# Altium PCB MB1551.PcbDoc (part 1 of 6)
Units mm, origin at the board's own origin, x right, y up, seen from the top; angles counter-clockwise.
Board outline 100 x 70 mm, 6 copper layers (Top Layer, Signal Layer 1, Signal Layer 2, Signal Layer 3, Signal Layer 4, Bottom Layer), stack 1.49 mm thick; 313 components, 266 nets, 1510 pads, 1089 vias.
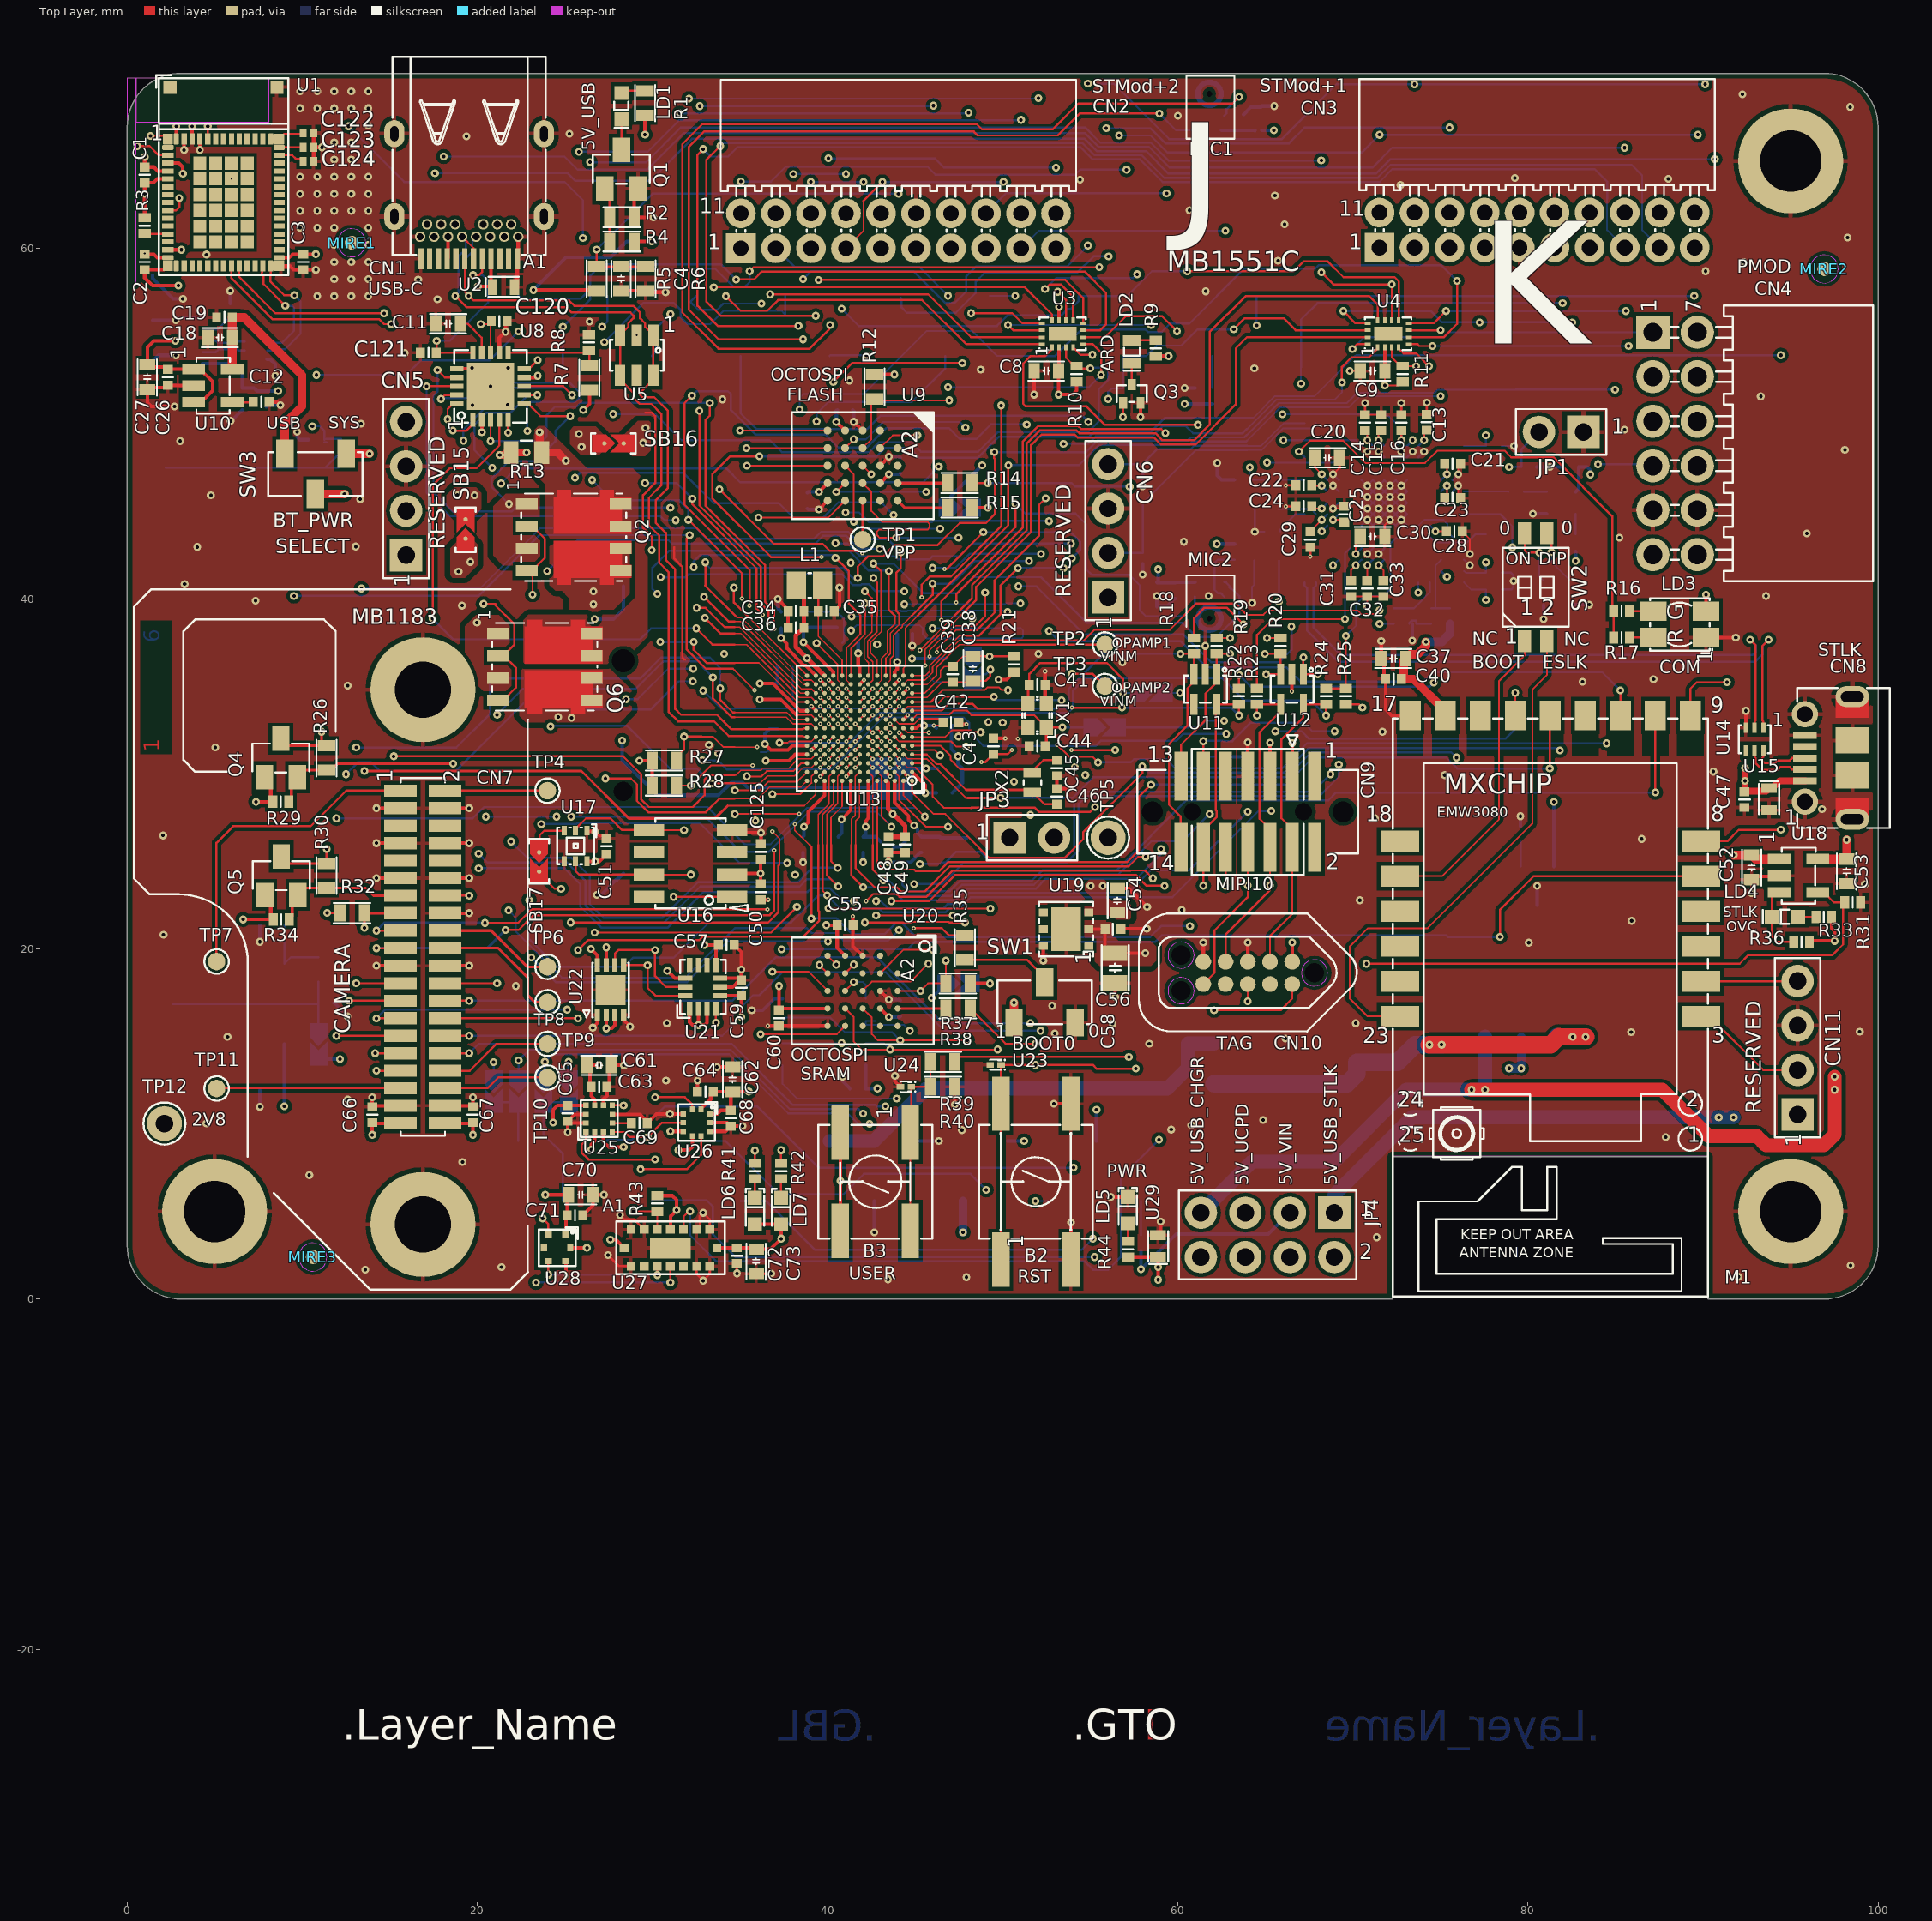
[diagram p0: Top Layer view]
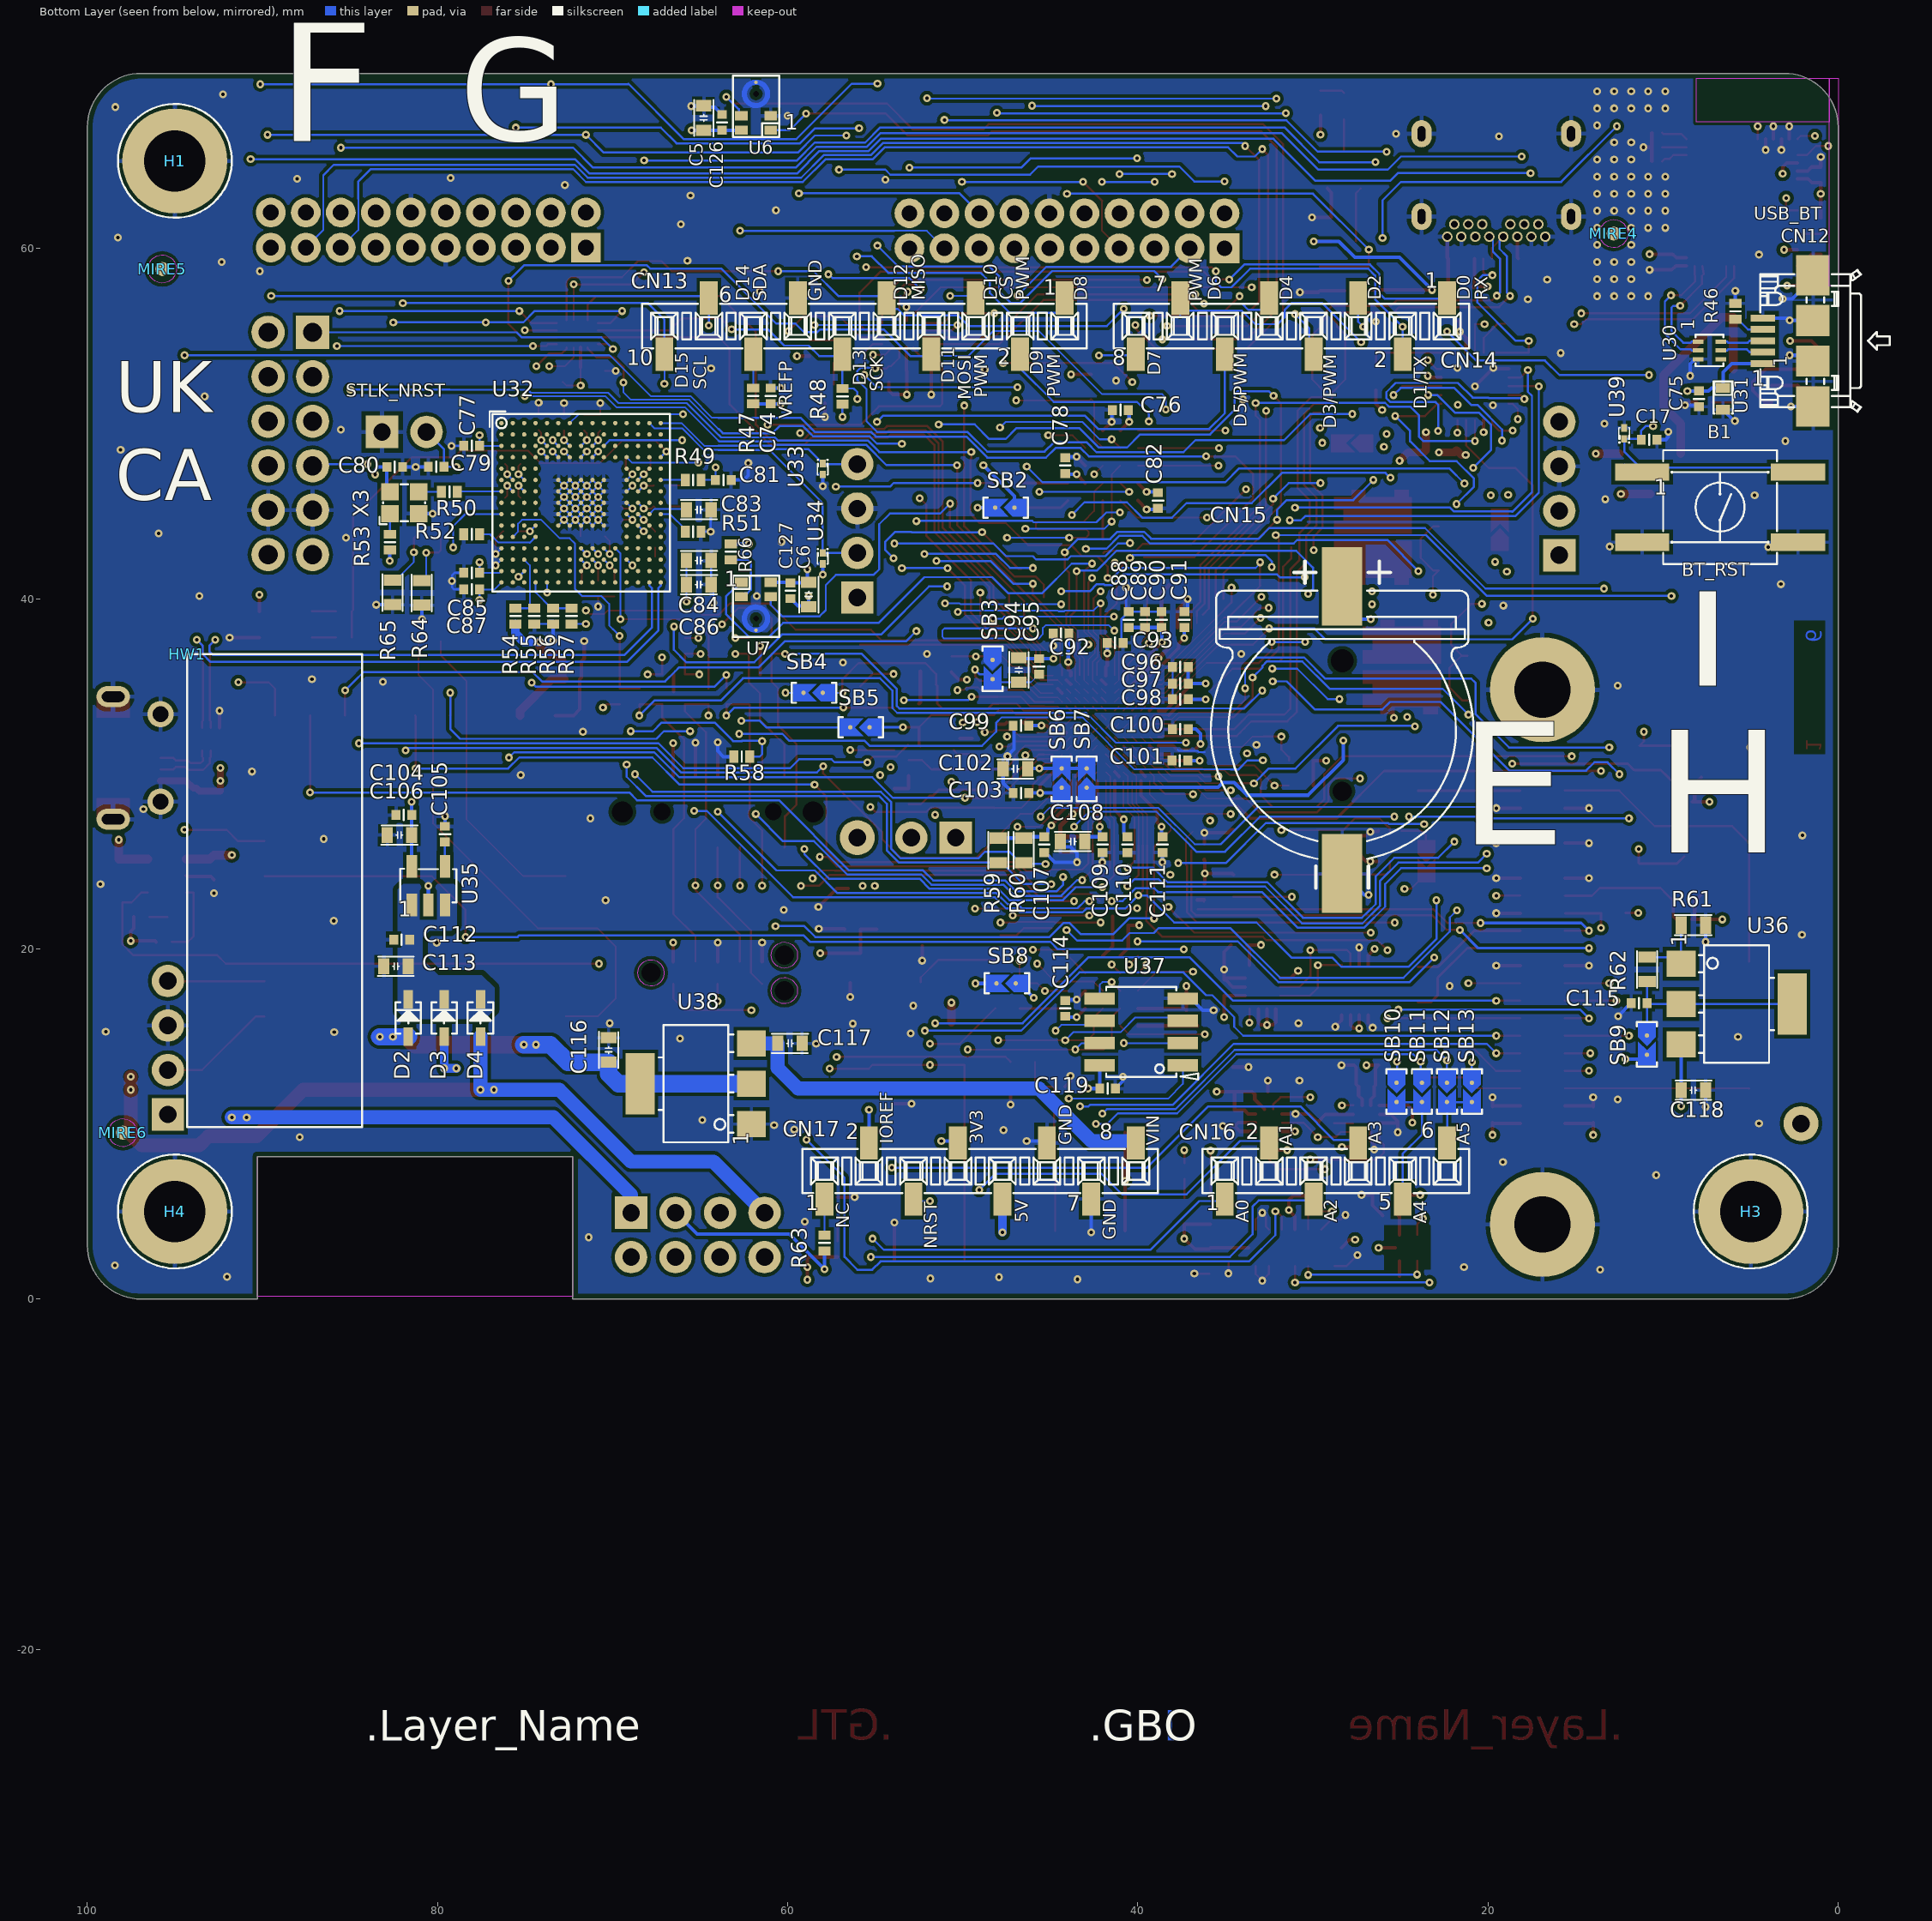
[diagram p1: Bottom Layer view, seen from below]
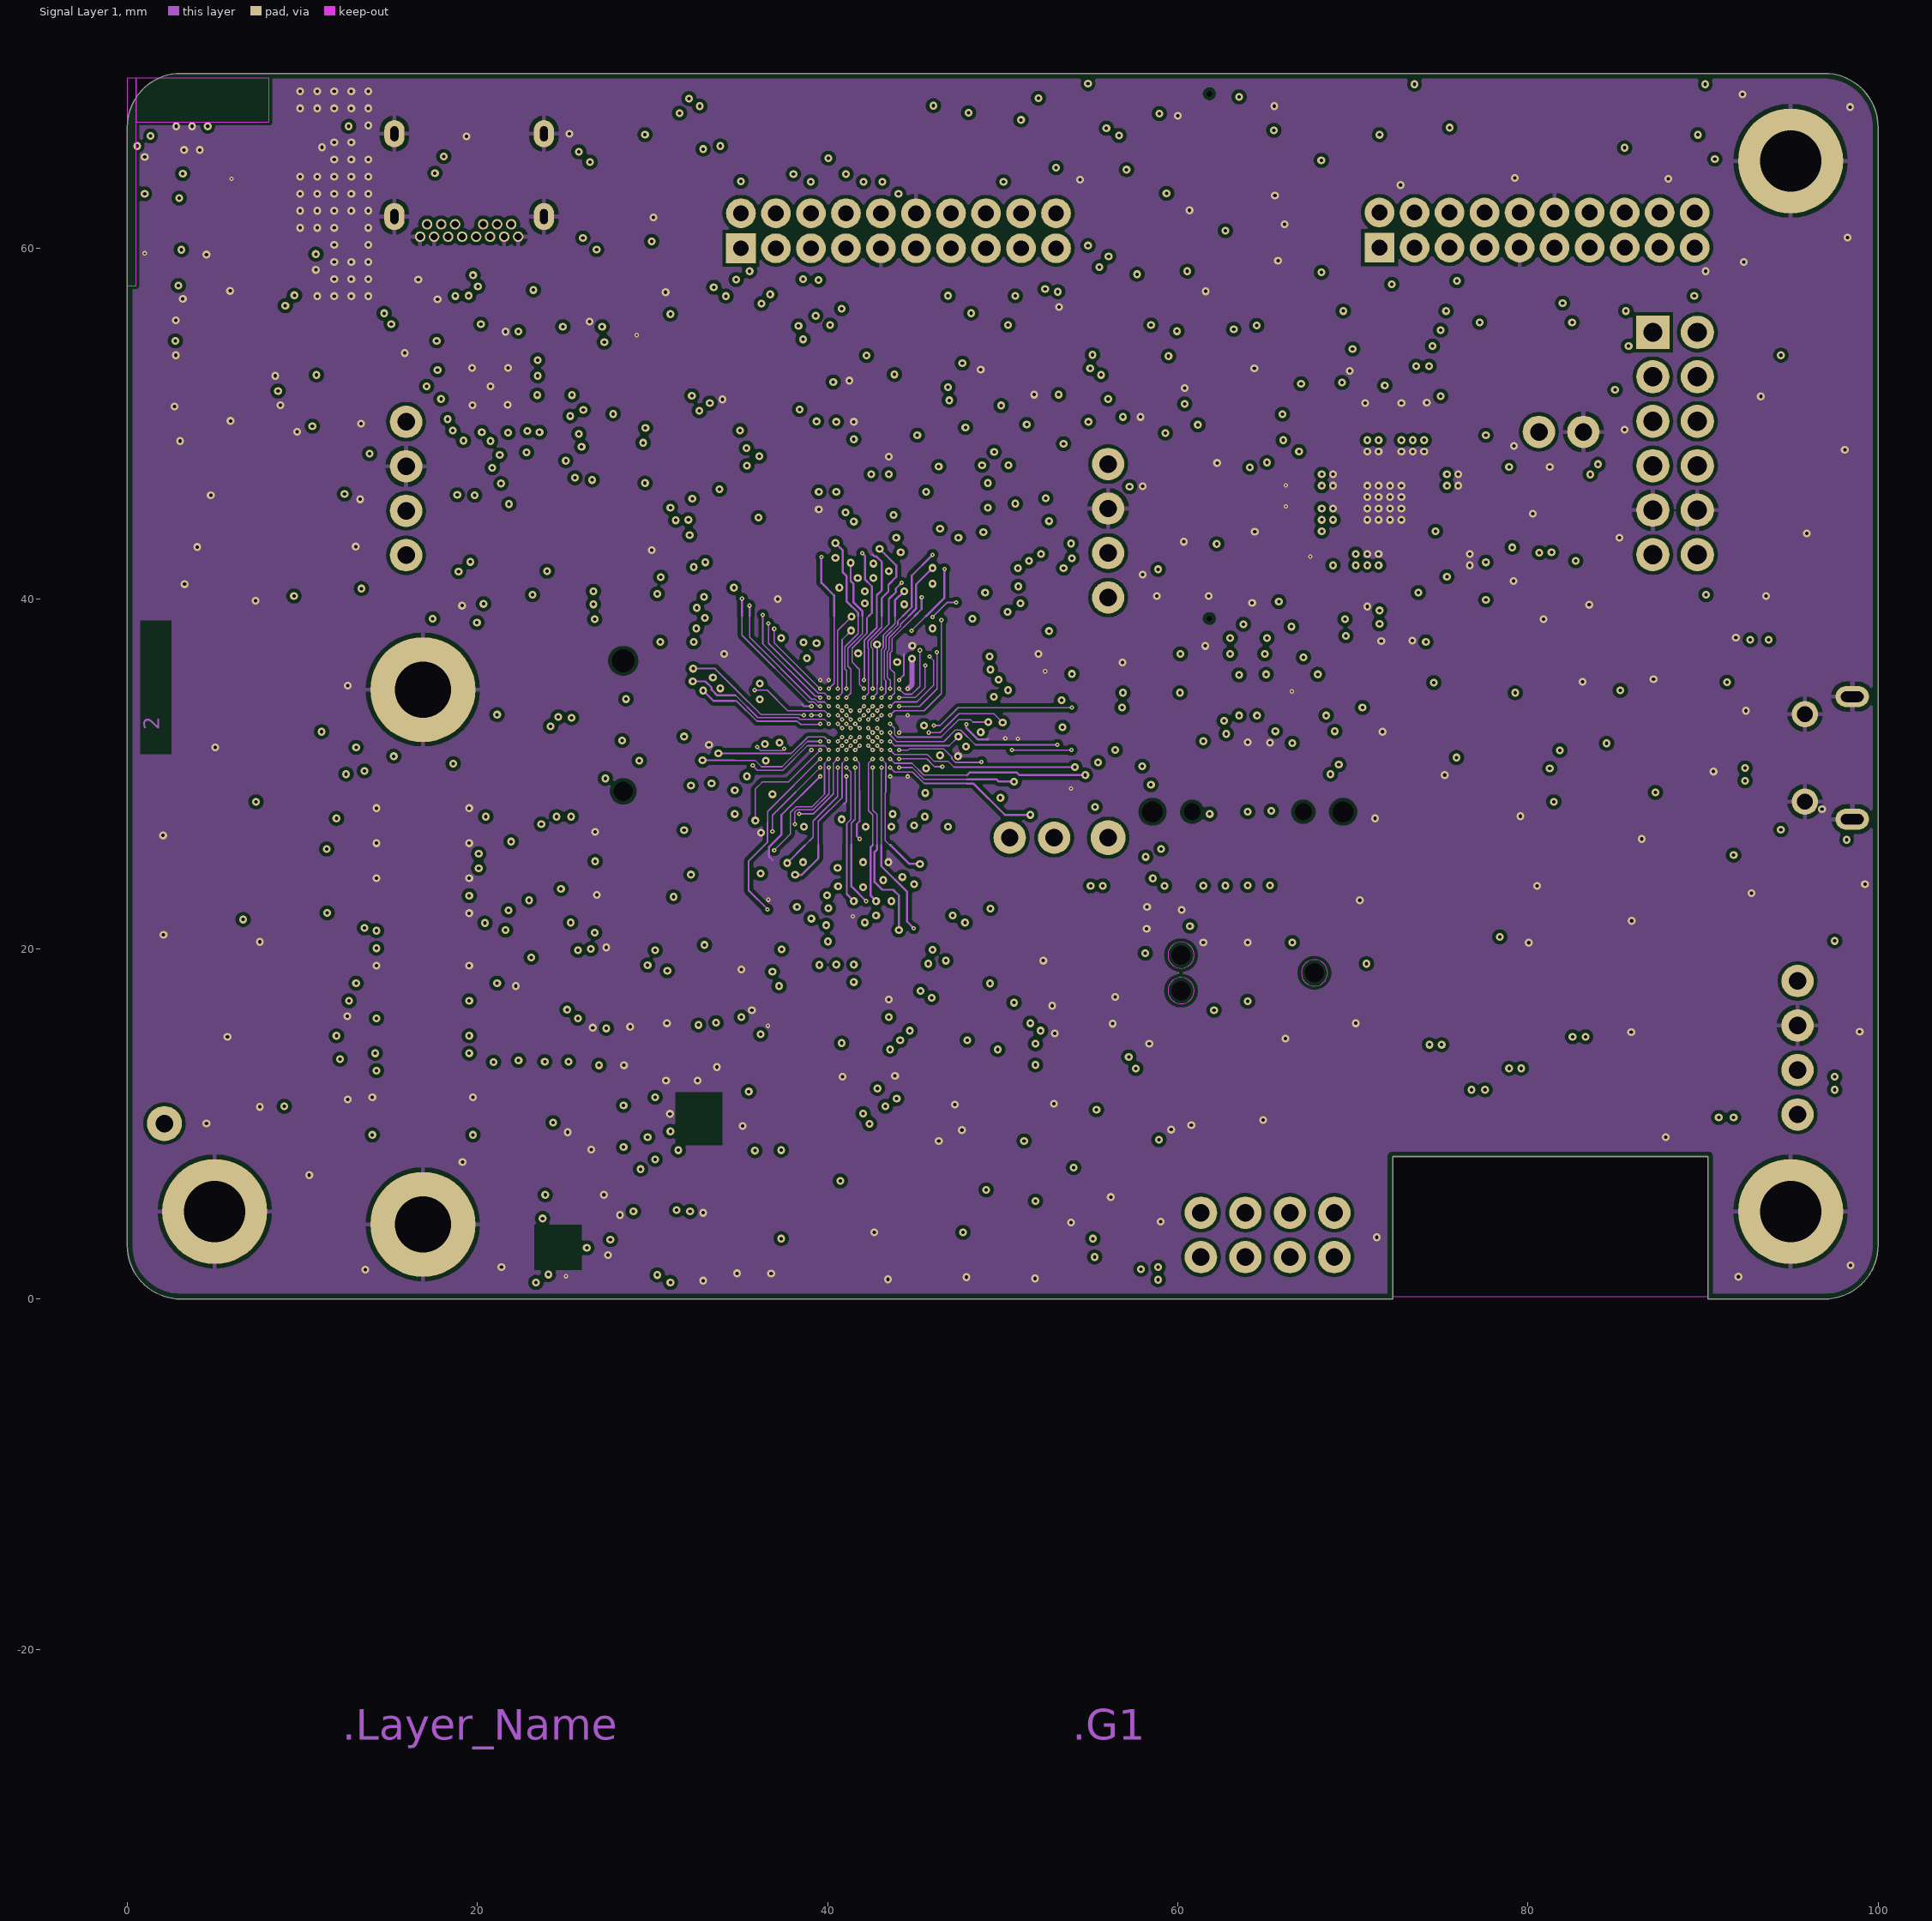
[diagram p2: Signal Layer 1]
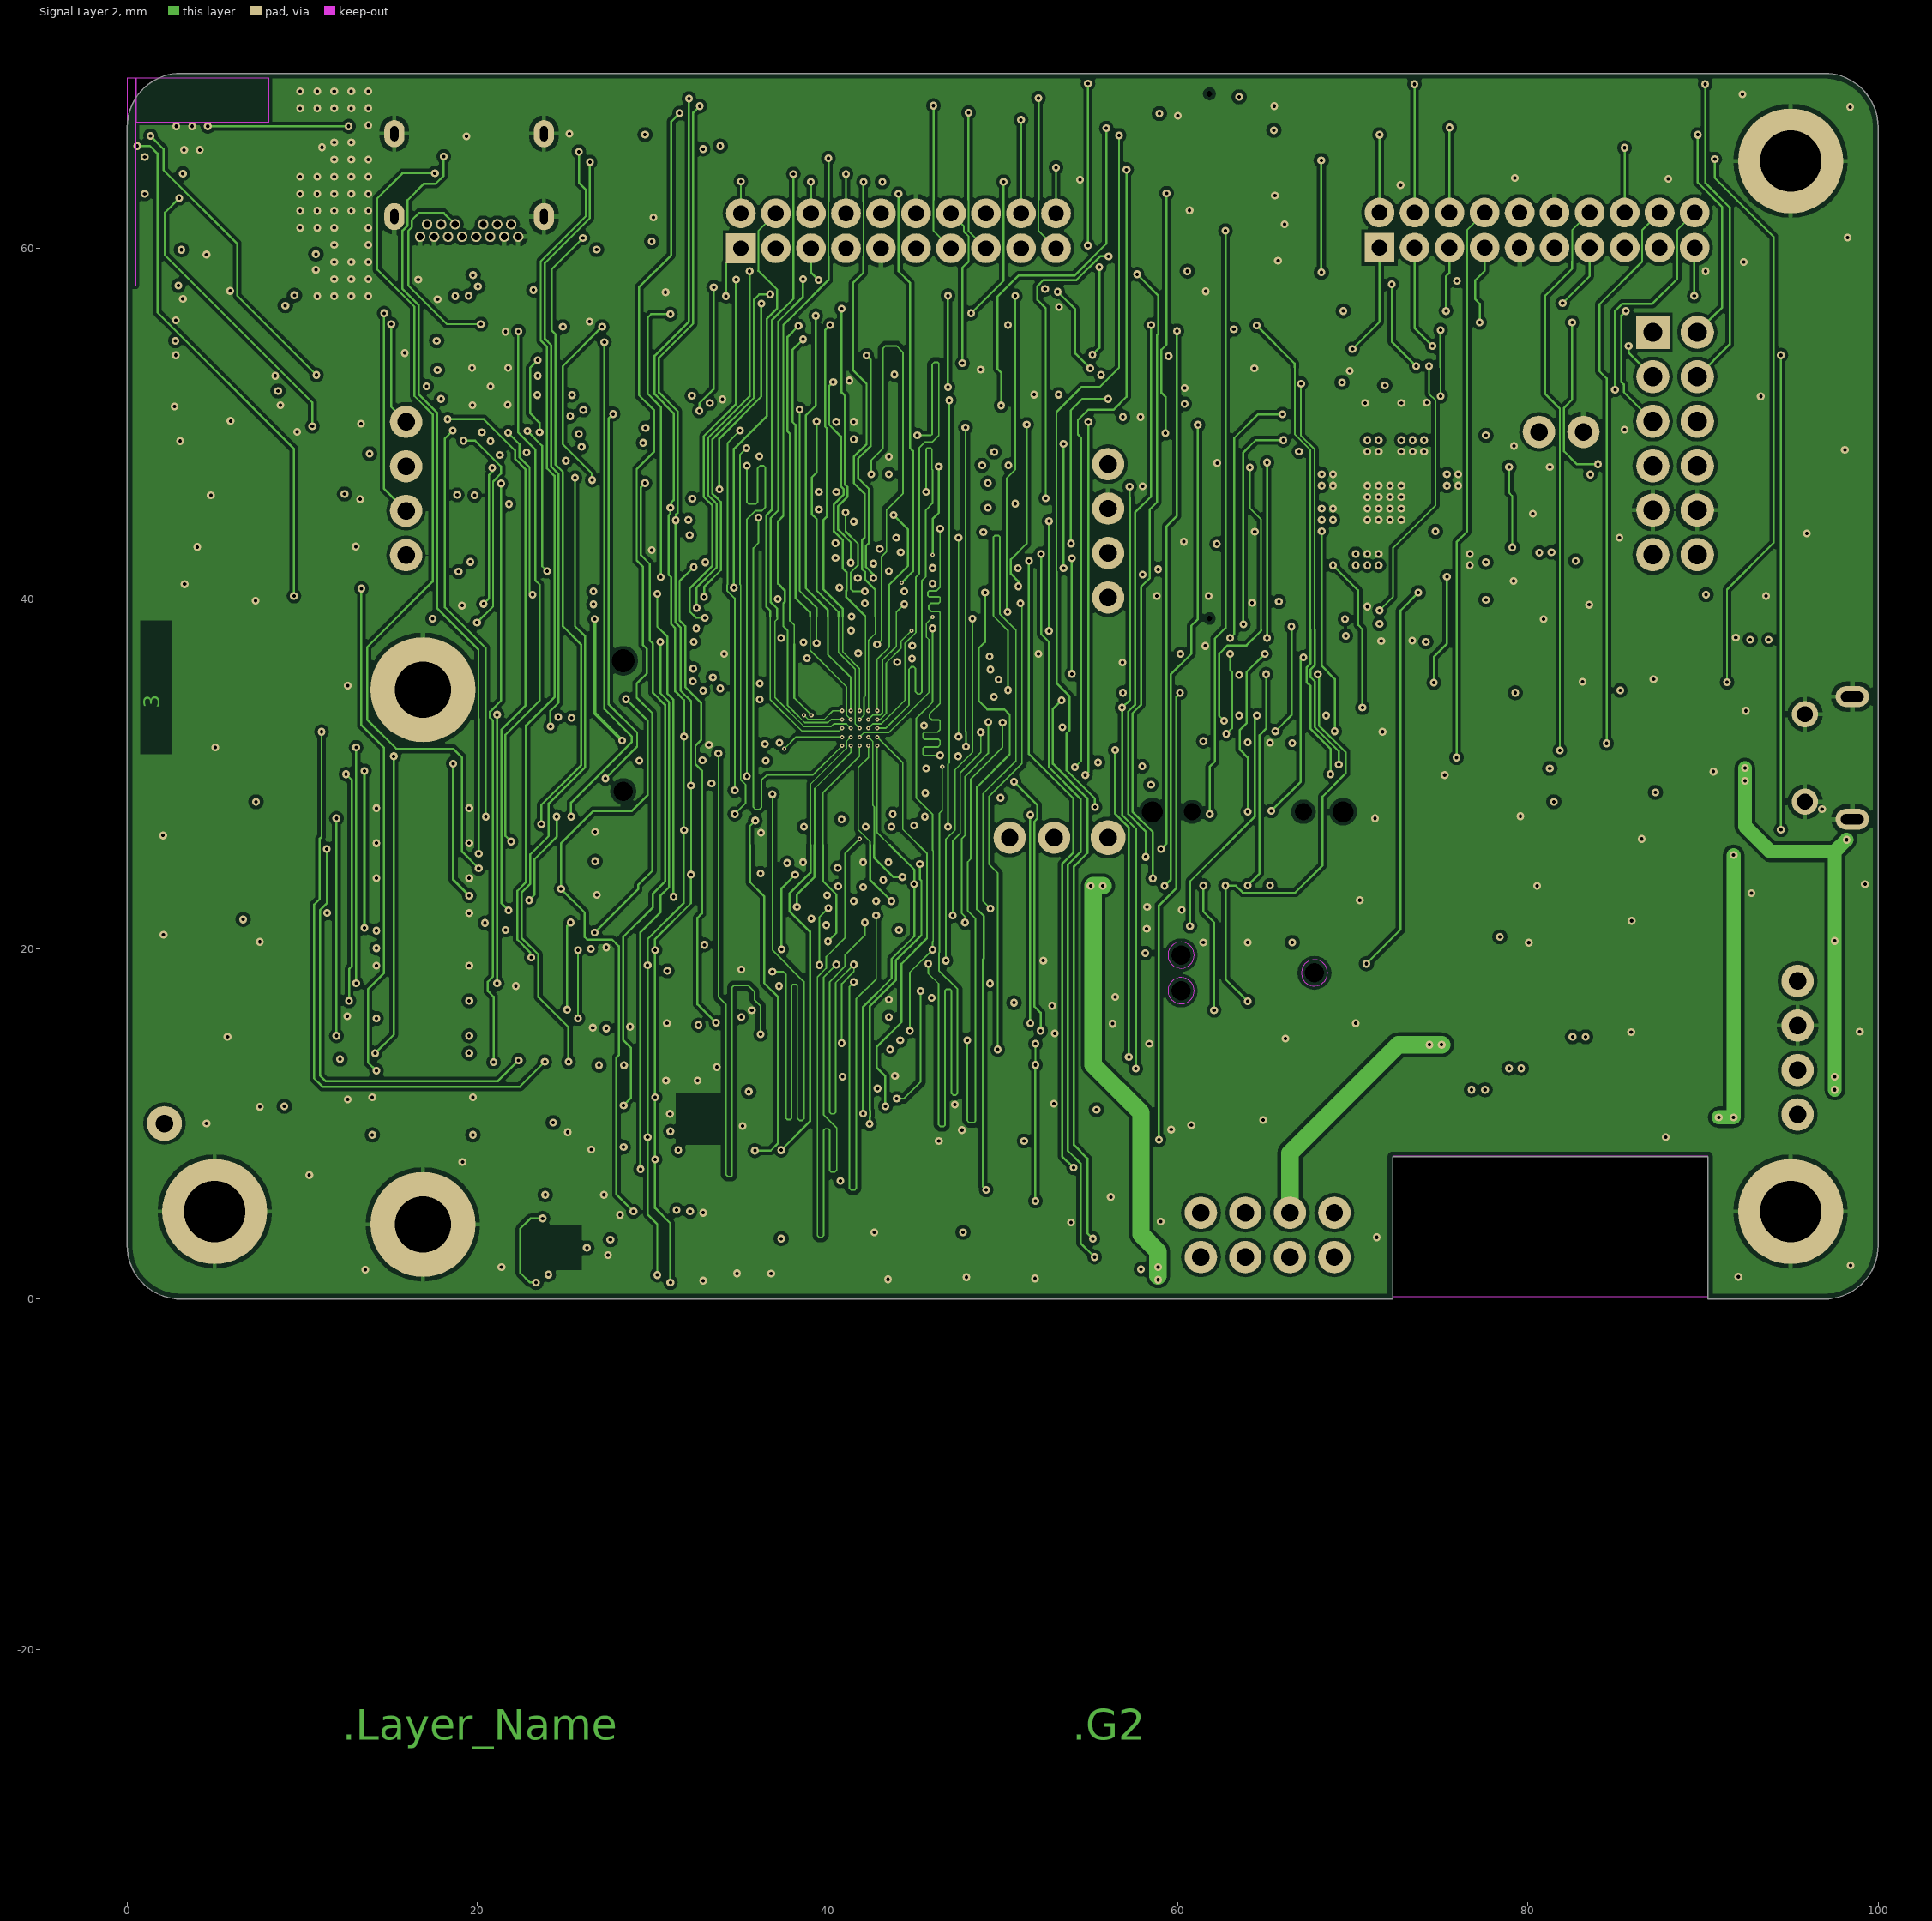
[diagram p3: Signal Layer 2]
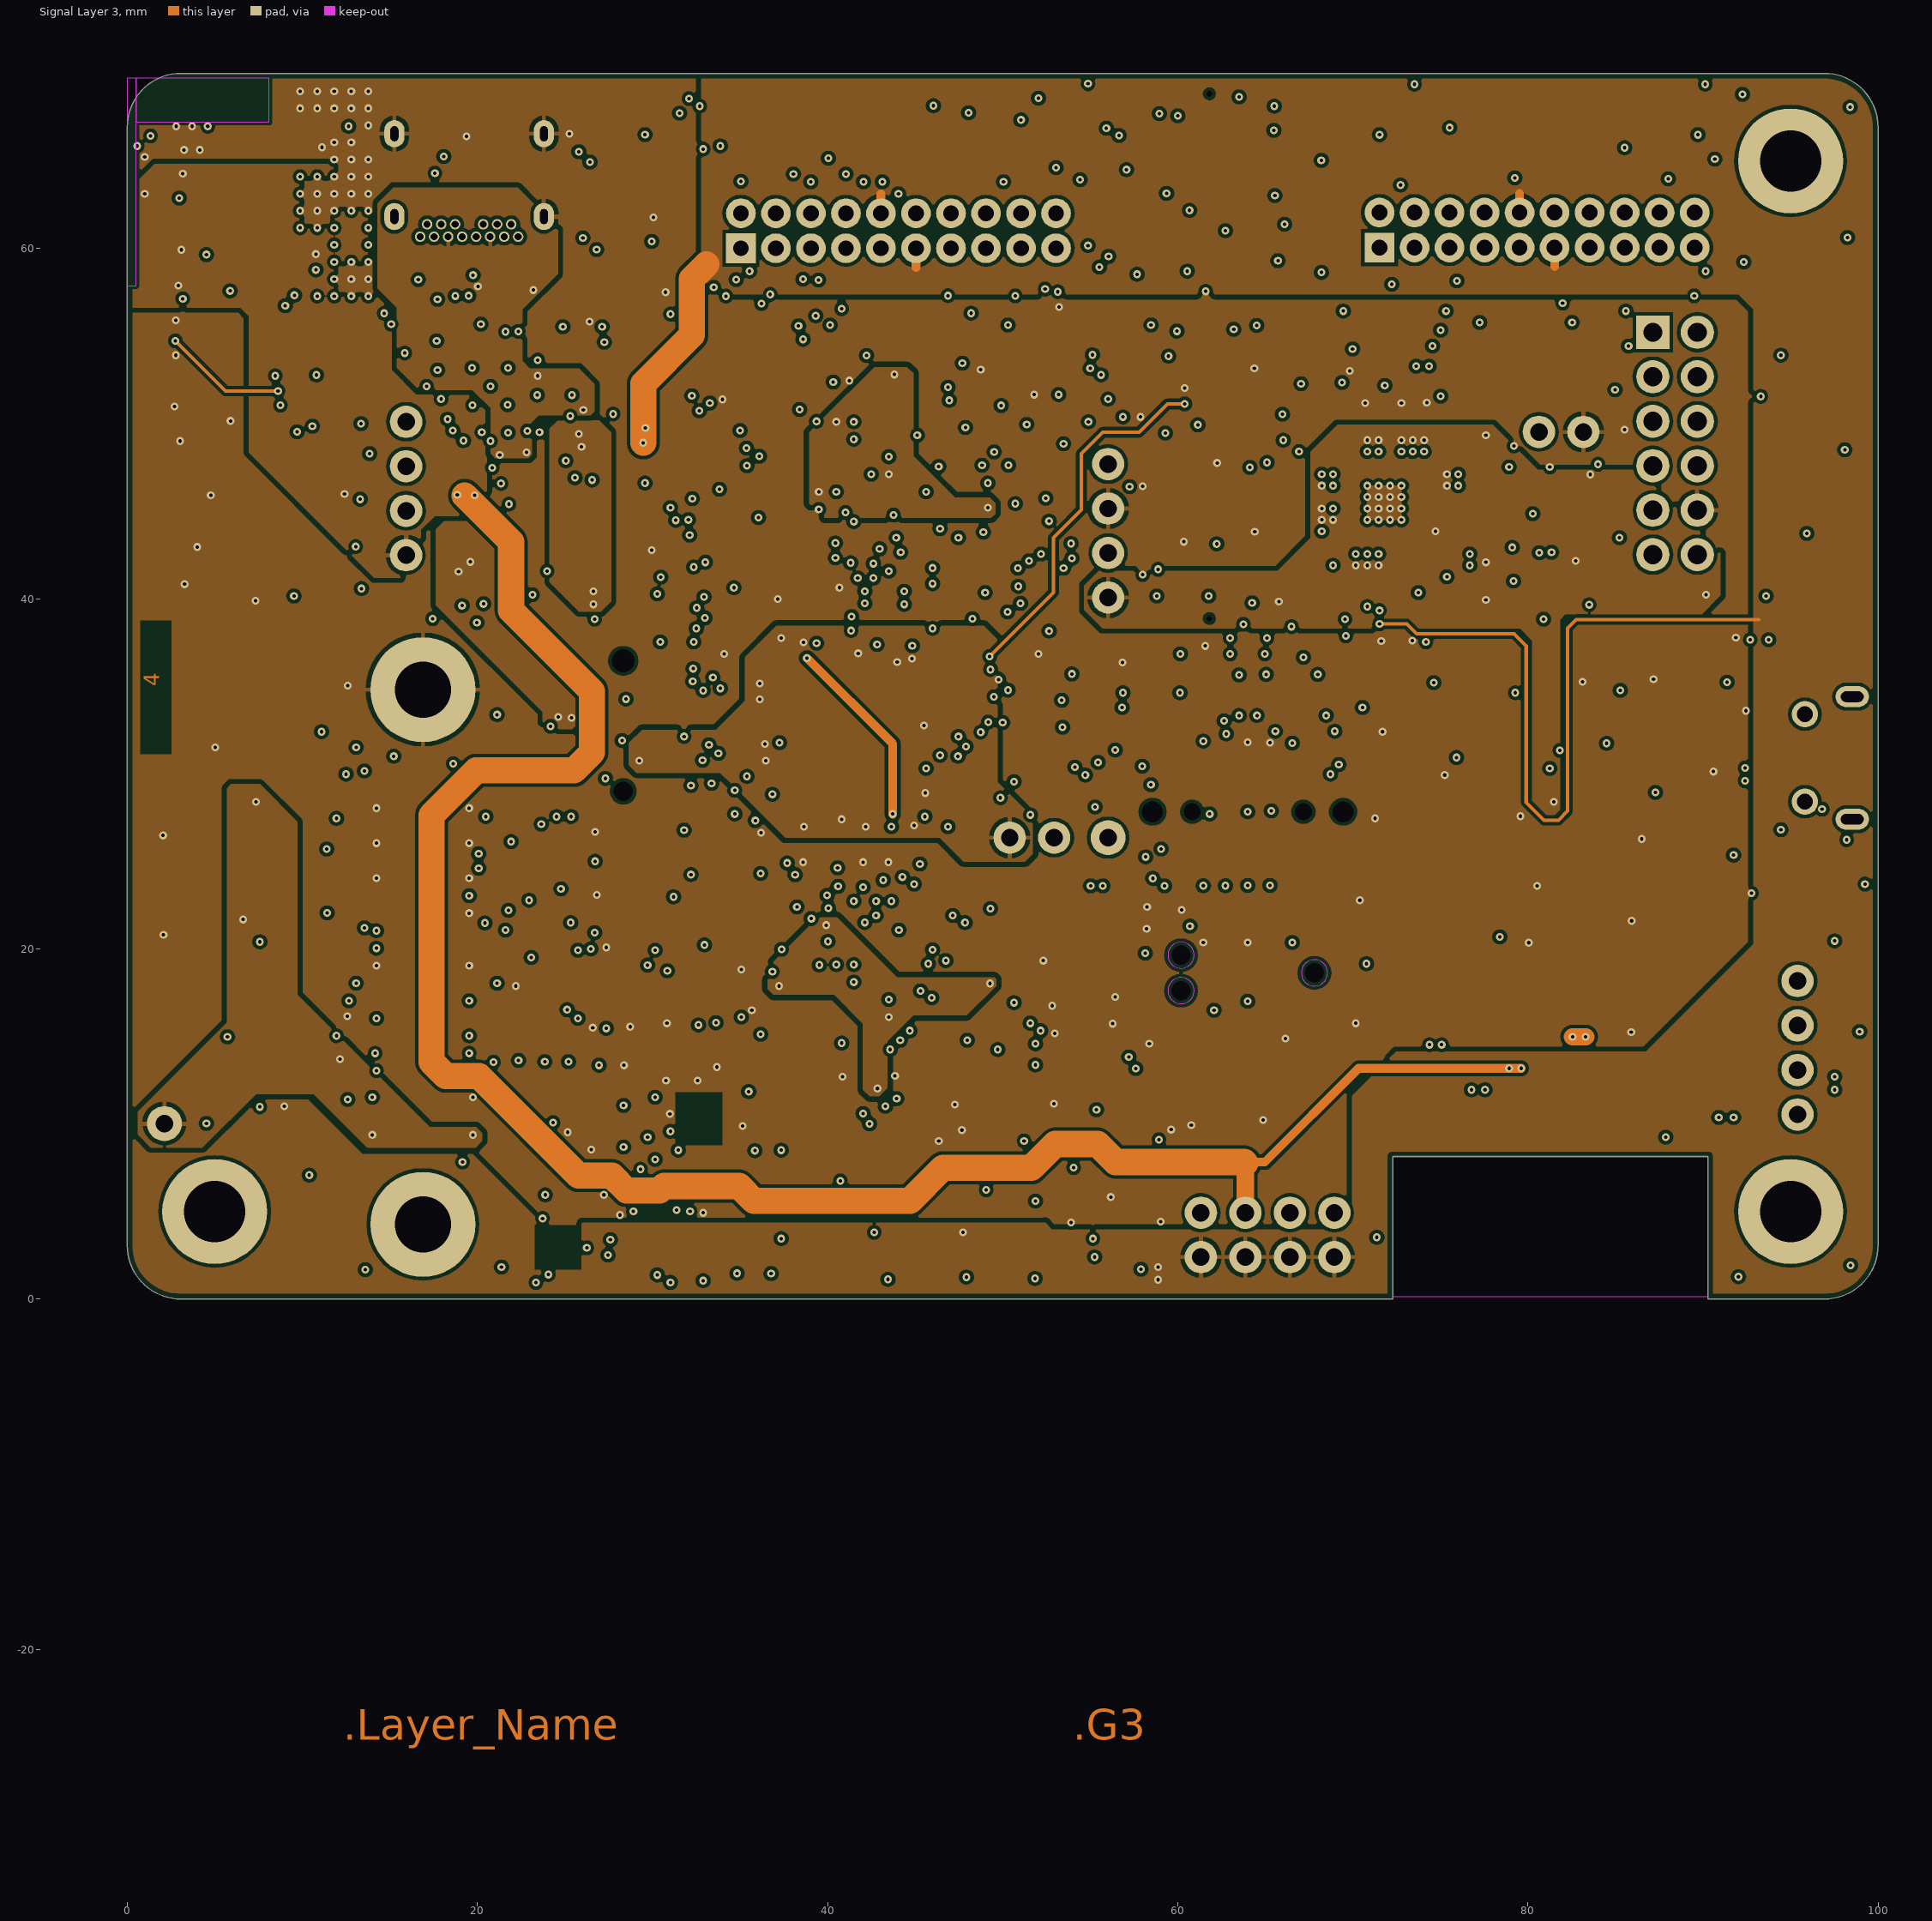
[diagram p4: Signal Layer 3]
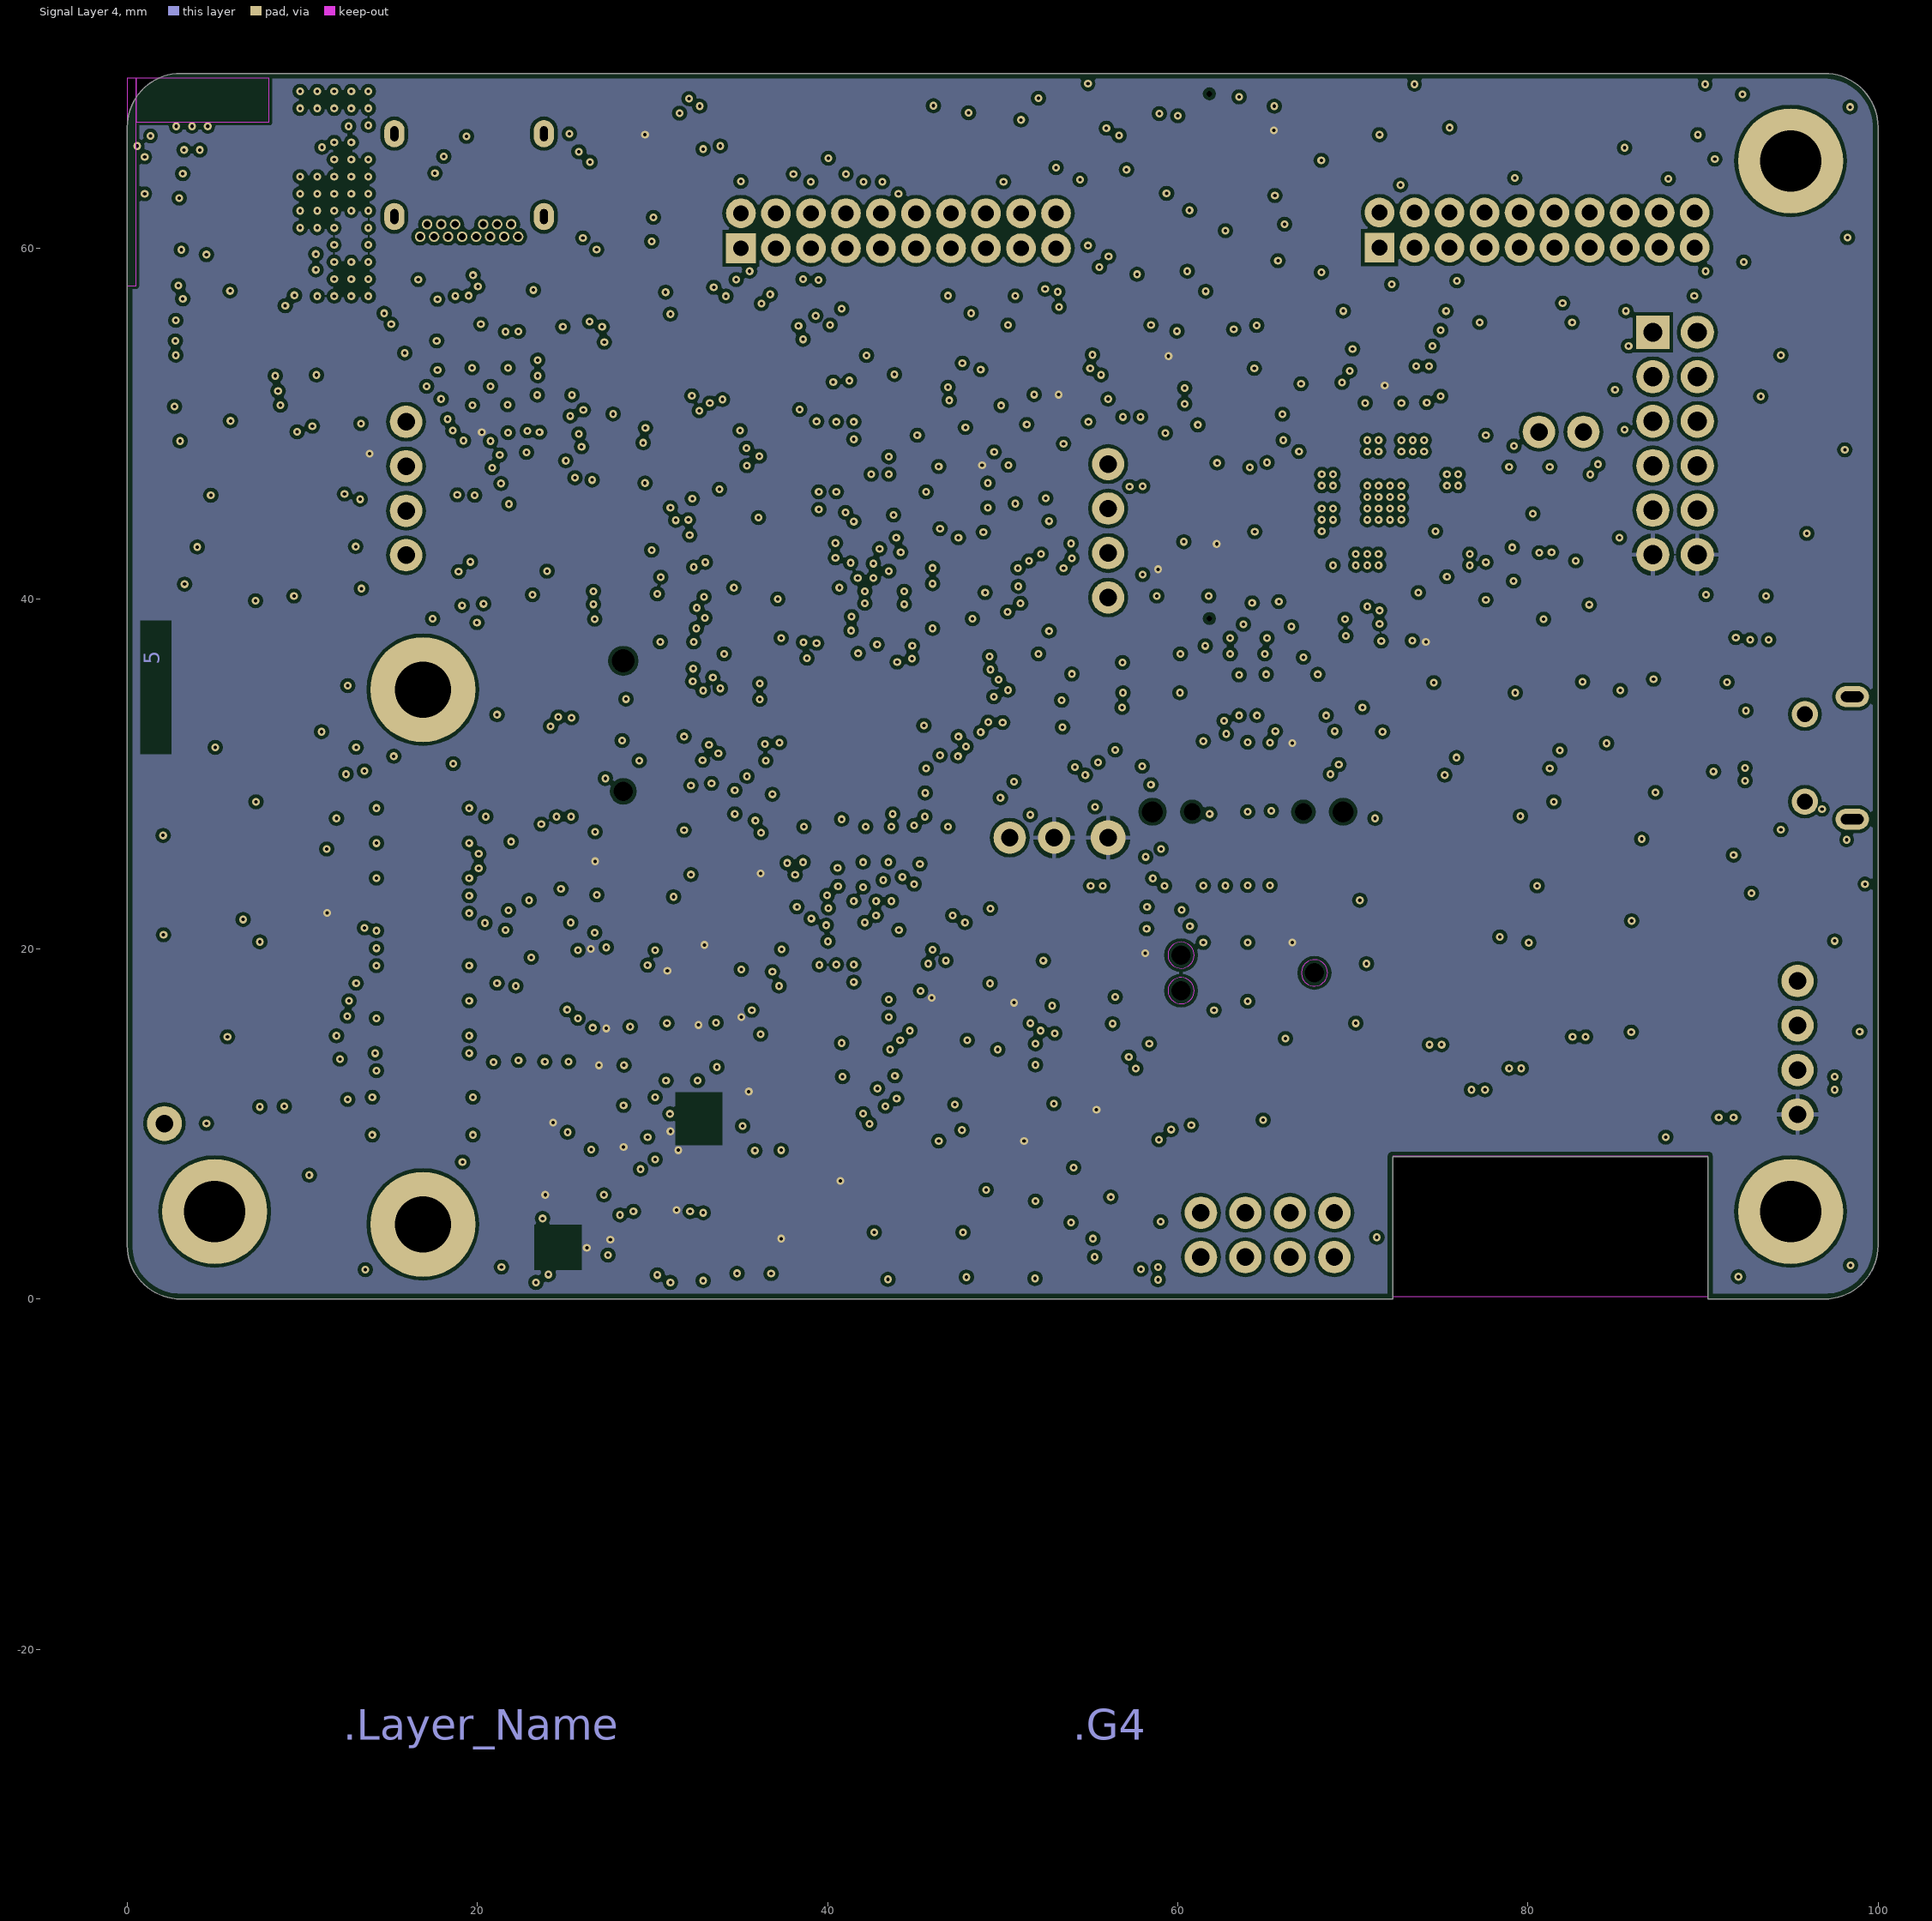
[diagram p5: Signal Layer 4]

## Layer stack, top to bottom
Top Solder: solder mask 0.015, Solder Resist, Dk 3.5
Top Layer: signal copper 0.035
Dielectric 1: dielectric 0.07, TU-768P, Dk 3.85
Signal Layer 1: signal copper 0.035
Dielectric2: dielectric 0.07, TU-768P, Dk 3.85
Signal Layer 2: signal copper 0.035
Dielectric3: dielectric 1, TU-768, Dk 4.5
Signal Layer 3: signal copper 0.035
Dielectric4: dielectric 0.07, TU-768P, Dk 3.85
Signal Layer 4: signal copper 0.035
Dielectric5: dielectric 0.07, TU-768P, Dk 3.85
Bottom Layer: signal copper 0.035
Bottom Solder: solder mask 0.015, Solder Resist, Dk 3.5

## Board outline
0,3.061 0,66.928 cw(c3.072,66.928) 3.072,70 96.927,70 cw(c96.927,66.927) 100,66.927 100,3.065 cw(c96.935,3.065) 96.935,0 90.28,0 90.28,8.125 72.28,8.125 72.28,0 3.061,0 cw(c3.061,3.061)

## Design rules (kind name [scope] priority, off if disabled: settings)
BoardOutlineClearance [All] p1: gap=0.3 ignorepadtopadclearanceinfootprint=FALSE except(0: Arc-SplitContinuation Track-SplitContinuation SMDPad-SplitContinuation THPad-SplitContinuation Via-SplitContinuation Fill-SplitContinuation Poly-SplitContinuation Region-SplitContinuation Text-SplitContinuation)
Clearance Clearance_Diff_90Ohms [InNetClass('Diff_90Ohms') vs InNet('GND')] p1: gap=0.12 ignorepadtopadclearanceinfootprint=FALSE except(0: Arc-Hole Track-Hole SMDPad-Hole THPad-Hole Via-Hole Fill-Hole Poly-Hole Region-Hole Text-Hole; 0.15: SMDPad-SMDPad; 0.2: Arc-Fill Arc-Poly Track-Fill SMDPad-THPad SMDPad-Fill SMDPad-Poly THPad-THPad THPad-Fill THPad-Poly Via-Fill Via-Poly Fill-Poly; 0.22: Track-Track Track-Poly; 0.3: Fill-Fill Poly-Poly)
Clearance Clearance_BGA_STLINK [WithinRoom('RoomDefinition_1')and TouchesRoom('RoomDefinition_1')] p2: gap=0.09 ignorepadtopadclearanceinfootprint=FALSE except(0: Arc-Hole Track-Hole SMDPad-Hole THPad-Hole Via-Hole Fill-Hole Poly-Hole Region-Hole Text-Hole; 0.15: SMDPad-SMDPad; 0.2: Arc-Fill Arc-Poly Track-Fill Track-Poly SMDPad-THPad SMDPad-Fill SMDPad-Poly THPad-THPad THPad-Fill THPad-Poly Via-Fill Via-Poly Fill-Poly; 0.3: Fill-Fill Poly-Poly)
Clearance Clearance_BGA_MCU [WithinRoom('RoomDefinition')and TouchesRoom('RoomDefinition')] p3: gap=0.085 ignorepadtopadclearanceinfootprint=FALSE except(0: Arc-Hole Track-Hole SMDPad-Hole THPad-Hole Via-Hole Fill-Hole Poly-Hole Region-Hole Text-Hole; 0.12: Track-Fill Via-Fill; 0.15: SMDPad-SMDPad; 0.2: Arc-Fill Arc-Poly Track-Poly SMDPad-THPad SMDPad-Fill SMDPad-Poly THPad-THPad THPad-Fill THPad-Poly Via-Poly Fill-Poly; 0.3: Fill-Fill Poly-Poly)
Clearance Clearance_50Ohms [InNetClass('50Ohms')] p4: gap=0.12 ignorepadtopadclearanceinfootprint=FALSE except(0: Arc-Hole Track-Hole SMDPad-Hole THPad-Hole Via-Hole Fill-Hole Poly-Hole Region-Hole Text-Hole; 0.2: Arc-Fill Arc-Poly SMDPad-THPad SMDPad-Fill SMDPad-Poly THPad-THPad THPad-Fill THPad-Poly Via-Fill Via-Poly Fill-Poly; 0.25: Arc-Track Track-Track Track-Fill Track-Poly Track-Region Track-Text SMDPad-SMDPad; 0.3: Fill-Fill Poly-Poly)
Clearance [All] p5: gap=0.12 ignorepadtopadclearanceinfootprint=FALSE except(0: Arc-Hole Track-Hole SMDPad-Hole THPad-Hole Via-Hole Fill-Hole Poly-Hole Region-Hole Text-Hole; 0.1: Track-THPad; 0.15: SMDPad-SMDPad; 0.2: Arc-Fill Arc-Poly Track-Fill Track-Poly SMDPad-THPad SMDPad-Fill SMDPad-Poly THPad-THPad THPad-Fill THPad-Poly Via-Fill Via-Poly Fill-Poly; 0.3: Fill-Fill Poly-Poly)
ComponentClearance [All] p1: gap=0.2 collisioncheckmode=3 verticalgap=0.2 showdistances=FALSE
DiffPairsRouting DiffPairsRouting_90Ohms [InDifferentialPairClass('Differential_Pairs_90Ohms')] p1: maxlimit=0.28 minlimit=0.2 mostfreqgap=0.2 toplayer_mingap=0.26 toplayer_maxgap=0.26 toplayer_prefgap=0.26 toplayer_minwidth=0.12 toplayer_maxwidth=0.12 toplayer_prefwidth=0.12 midlayer1_maxgap=0.2 midlayer1_minwidth=0.12 midlayer1_maxwidth=0.12 midlayer1_prefwidth=0.12 midlayer2_mingap=0.28 midlayer2_prefgap=0.28 midlayer2_minwidth=0.097 midlayer2_maxwidth=0.097 midlayer2_prefwidth=0.097 midlayer3_maxgap=0.2 midlayer3_minwidth=0.12 midlayer3_maxwidth=0.12 midlayer3_prefwidth=0.12 midlayer4_maxgap=0.2 midlayer4_minwidth=0.12 midlayer4_maxwidth=0.12 midlayer4_prefwidth=0.12 bottomlayer_mingap=0.26 bottomlayer_maxgap=0.26 bottomlayer_prefgap=0.26 bottomlayer_minwidth=0.12 bottomlayer_maxwidth=0.12 bottomlayer_prefwidth=0.12 maxuncoupledlength=12.7
HoleSize [All] p1: absolutevalues=TRUE maxlimit=10 minlimit=0.025 maxpercent=80.000 minpercent=20.000
HoleToHoleClearance [InDrillLayerPair('Top Layer - Bottom Layer') vs InDrillLayerPair('Top Layer - Bottom Layer')] p1: gap=0.5 allowstackedmicrovias=TRUE
MatchedLengths MatchedLengths_OctoSPI_F [InNetClass('OctoSPI_F')] p1: tolerance=7 checknetsindiffpair=FALSE checkdiffpairvsdiffpair=TRUE checkxsignals=TRUE checkothers=TRUE
MatchedLengths MatchedLengths_OctoSPI_R [InNetClass('OctoSPI_R')] p2: tolerance=7 checknetsindiffpair=FALSE checkdiffpairvsdiffpair=TRUE checkxsignals=TRUE checkothers=TRUE
MaxMinImpedance "Schematic Impedance Constraint_3" [InNet('USB_DEV_HS_P')] p1: minimum=85,00 maximum=95,00
MaxMinImpedance "Schematic Impedance Constraint_2" [InNet('USB_DEV_HS_N')] p2: minimum=85,00 maximum=95,00
MaxMinImpedance "Schematic Impedance Constraint_1" [InNet('USB_DEV_HS_CN_N')] p3: minimum=85,00 maximum=95,00
MaxMinImpedance "Schematic Impedance Constraint" [InNet('USB_DEV_HS_CN_P')] p4: minimum=85,00 maximum=95,00
MinimumSolderMaskSliver [All] p1: minsoldermaskwidth=0.1
PolygonConnect PolygonConnect_NO_FT [IsNamedPolygon('NO_FT')] p1: thpad.connectstyle=Relief thpad.reliefconductorwidth=0.25 thpad.reliefentries=4 thpad.polygonreliefangle="90 Angle" thpad.airgapwidth=0.25 smdpad.connectstyle=Direct smdpad.reliefconductorwidth=0.254 smdpad.reliefentries=4 smdpad.polygonreliefangle="90 Angle" smdpad.airgapwidth=0.254 via.connectstyle=Direct via.reliefconductorwidth=0.254 via.reliefentries=4 via.polygonreliefangle="90 Angle" via.airgapwidth=0.254
PolygonConnect [All] p2: thpad.connectstyle=Relief thpad.reliefconductorwidth=0.25 thpad.reliefentries=4 thpad.polygonreliefangle="90 Angle" thpad.airgapwidth=0.25 smdpad.connectstyle=Relief smdpad.reliefconductorwidth=0.2 smdpad.reliefentries=4 smdpad.polygonreliefangle="90 Angle" smdpad.airgapwidth=0.2 via.connectstyle=Direct via.reliefconductorwidth=0.2 via.reliefentries=4 via.polygonreliefangle="90 Angle" via.airgapwidth=0.2
RoomDefinition [InComponentClass('Room Definition 1') vs False] p1: confinementstyle=ConfineIn formatcopy=TRUE lockcomponents=FALSE outline 34.7,39 47.975,39 47.975,25.925 34.7,25.925
RoomDefinition RoomDefinition_1 [InComponentClass('Room Definition 1')] p2: confinementstyle=ConfineIn formatcopy=TRUE lockcomponents=FALSE outline 79.325,38.25 63.95,38.25 63.95,53.2 79.325,53.2
RoutingVias RoutingVias_SL4/BOTTOM [InDrillLayerPair('Signal Layer 4 - Bottom Layer')] p1: holewidth=0.1 width=0.25 viastyle="Through Hole" minholewidth=0.1 minwidth=0.25 maxholewidth=0.1 maxwidth=0.25
RoutingVias RoutingVias_SL3/SL4 [InDrillLayerPair('No Drill Pair')] p2: holewidth=0.1 width=0.25 viastyle="Through Hole" minholewidth=0.1 minwidth=0.25 maxholewidth=0.1 maxwidth=0.25
RoutingVias RoutingVias_SL1/SL2 [InDrillLayerPair('Signal Layer 1 - Signal Layer 2')] p3: holewidth=0.1 width=0.25 viastyle="Through Hole" minholewidth=0.1 minwidth=0.25 maxholewidth=0.1 maxwidth=0.25
RoutingVias RoutingVias_TOP/SL1 [InDrillLayerPair('Top Layer - Signal Layer 1')] p4: holewidth=0.1 width=0.25 viastyle="Through Hole" minholewidth=0.1 minwidth=0.25 maxholewidth=0.1 maxwidth=0.25
RoutingVias RoutingVias_TOP/BOTTOM [InDrillLayerPair('Top Layer - Bottom Layer')] p5: holewidth=0.2 width=0.45 viastyle="Through Hole" minholewidth=0.2 minwidth=0.45 maxholewidth=0.2 maxwidth=0.45
SilkToSilkClearance [All] p1: silktosilkclearance=0.2
SilkToSolderMaskClearance [IsPad] p1: minsilkscreentomaskgap=0.2 clearancetoexposedcopper=TRUE
SolderMaskExpansion [All] p1: expansion=0.102 istentingtop=FALSE
Width Width_BGA_STLINK [WithinRoom('RoomDefinition_1')and TouchesRoom('RoomDefinition_1')] p1: maxlimit=0.25 minlimit=0.09 preferedwidth=0.1
Width Width_BGA_MCU [WithinRoom('RoomDefinition')and TouchesRoom('RoomDefinition')] p2: maxlimit=0.25 minlimit=0.08 preferedwidth=0.1
Width Width_50Ohms [InNetClass('50Ohms')] p3: maxlimit=0.1 minlimit=0.08 preferedwidth=0.09 toplayer_minwidth=0.1 toplayer_prefwidth=0.1 midlayer1_maxwidth=0.08 midlayer1_prefwidth=0.08 midlayer2_minwidth=0.09 midlayer2_maxwidth=0.09 midlayer3_minwidth=0.09 midlayer3_maxwidth=0.09 midlayer4_maxwidth=0.08 midlayer4_prefwidth=0.08 bottomlayer_minwidth=0.1 bottomlayer_prefwidth=0.1 minimp=50.000000 maximp=50.000000 favimp=50.000000
Width Width_Alim [InNetClass('Alim')] p4: maxlimit=1.5 minlimit=0.12 preferedwidth=0.2
Width [All] p5: maxlimit=1 minlimit=0.1 preferedwidth=0.12
23 further rules are at their usual default settings.

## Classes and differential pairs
net class Diff_90Ohms: NetCN12_2 NetCN12_3 USB.C_N USB.C_P USB_DEV_HS_CN_N USB_DEV_HS_CN_P USB_DEV_HS_N USB_DEV_HS_P USB_DM USB_DP
net class Alim_500µm: 2V8 3V3_STLK
net class Alim_1,5mm: 3V3
net class Alim_800µm: 5V_USB_CHGR 5V_USB_STLK VBUS_C VIN
net class Alim_1mm: 5V 5V_VIN
net class OctoSPI_F: OCTOSPI.F_CLK_P OCTOSPI.F_DQS OCTOSPI.F_IO0 OCTOSPI.F_IO1 OCTOSPI.F_IO2 OCTOSPI.F_IO3 OCTOSPI.F_IO4 OCTOSPI.F_IO5 OCTOSPI.F_IO6 OCTOSPI.F_IO7 OCTOSPI.F_NCS
net class OctoSPI_R: OCTOSPI.R_CLK_P OCTOSPI.R_DQS OCTOSPI.R_IO0 OCTOSPI.R_IO1 OCTOSPI.R_IO2 OCTOSPI.R_IO3 OCTOSPI.R_IO4 OCTOSPI.R_IO5 OCTOSPI.R_IO6 OCTOSPI.R_IO7 OCTOSPI.R_NCS
net class 50Ohms: OCTOSPI.F_CLK_P OCTOSPI.F_DQS OCTOSPI.F_IO0 OCTOSPI.F_IO1 OCTOSPI.F_IO2 OCTOSPI.F_IO3 OCTOSPI.F_IO4 OCTOSPI.F_IO5 OCTOSPI.F_IO6 OCTOSPI.F_IO7 OCTOSPI.F_NCS OCTOSPI.R_CLK_P OCTOSPI.R_DQS OCTOSPI.R_IO0 OCTOSPI.R_IO1 OCTOSPI.R_IO2 OCTOSPI.R_IO3 OCTOSPI.R_IO4 OCTOSPI.R_IO5 OCTOSPI.R_IO6 OCTOSPI.R_IO7 OCTOSPI.R_NCS
component class U_WIFI&BT_INTERPOSERS: B3 C1 C16 C18 C30 C39 C43 C53 C82 C101 C103 C108 CN3 CN6 HW9 M1 R37 R39 U1 U2 U36
component class U_USB_TYPEC: C42 C45 C89 C90 CN4 JP1 LD1 Q1 Q2 R1 R2 R5 R6 R13 R20 R27 R40 U2 U5 U8
component class U_STMod+: C9 C101 CN3 CN4 R11 R13 U5 U31
component class U_ST_LINK_V3E: C1 C9 C12 C14 C15 C23 C30 C32 C39 C53 C76 C79 C80 C81 C83 C84 C85 C86 C87 C90 C92 C93 C94 C96 C98 C99 C104 C105 C106 C108 C109 C111 C112 CN3 CN8 CN9 CN10 D2 D3 D4 HW8 JP1 LD1 LD2 R5 R15 R17 R18 R20 R22 R24 R27 R34 R41 R44 R49 R50 R51 R52 R53 R54 R55 R56 R57 R58 R61 U11 U12 U18 U22 U31 U32 U33 U34 U38 X3
component class U_OCTOSPI: C30 C53 C61 C76 C82 C114 C118 R12 R13 R14 R37 R38 SB2 SB8 TP1 U2 U5 U20
component class U_MEMs: C50 C53 C59 C60 C61 C63 C64 C65 C66 C69 C70 C71 C72 C80 C114 R41 R56 U11 U12 U13 U18 U19 U21 U26 U33 U34
component class U_Mechanical_Parts: H1 H3 H4 HW3 HW4 HW5
component class U_MCU_PWR: C9 C12 C16 C30 C32 C34 C35 C39 C48 C53 C89 C90 C92 C93 C94 C96 C97 C98 C100 C101 C102 C103 C105 C108 C109 C111 C118 C119 L1 SB3 SB7
component class U_MCU_IO: R20 R24 R27 R59 TP1 TP2 U33
component class U_MCU_CLOCK_&_RESET: B2 B3 C4 C39 C42 C43 C45 C61 HW1 HW2 LD2 LD6 R35 R37 R40 R52 R54 U20 U24 X1 X2
component class U_Camera: C53 C61 CN7 Q3 Q4 R24 R30 R34 R44 R52 TP4 TP5 TP6 TP7 TP8 TP9 TP10
component class U_BOARD_PWR: C50 C56 C69 C103 C108 C114 C118 HW1 JP1 LD5 R24 R44 R62 SB10 TP5 TP10 U12 U26 U36 U38
component class U_AUDIO: C39 C61 U2 U20
component class U_ARDUINO: C92 CN6 CN10 CN11 LD2 Q3 R5 R24 R48 R52 SB10 SB11 SB12 SB13
net class Alim: 2V8 3V3 3V3_BT 3V3_STLK 5V 5V_UCPD 5V_USB_CHGR 5V_USB_STLK 5V_VIN AGND GND VBUS_BT VBUS_C VDD_MCU VDD_OCTOSPI_FLASH VDD_OCTOSPI_SRAM VIN VREFP
differential pair USB_FS: +USB.C_P -USB.C_N
differential pair USB_DEV_HS: +USB_DEV_HS_P -USB_DEV_HS_N
differential pair USB_DEV_HS_CN: +USB_DEV_HS_CN_P -USB_DEV_HS_CN_N
differential pair USB_BT_CN: +NetCN12_3 -NetCN12_2
differential pair USB_BT: +USB_DP -USB_DM

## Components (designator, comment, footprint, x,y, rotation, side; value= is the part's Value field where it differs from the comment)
B1 "SW_BLACK_KSC321GLFS" SWI_C&K_KSC321GLFS_BLACK 6.75,45.225 r180 bottom value=KSC321GLFS
B2 "SW_BLACK_KSC321GLFS" SWI_C&K_KSC321GLFS_BLACK 51.9,6.7 r90 top value=KSC321GLFS
B3 "SW_BLUE_KSC721JLFS" SWI_C&K_KSC721JLFS_BLUE 42.725,6.7 r270 top value=KSC721JLFS
C1 "" C0402 1,64.2 r270 top value=100nF
C2 "" C0402 1,59.225 r270 top value=100nF
C3 "" C0402 10.05,59.225 r90 top value=100nF
C4 "" C0603 28.204,58.275 r90 top value=10pF
C5 "" C0603 64.8,67.45 r90 bottom value=1uF
C6 "" C0603 58.799,40.227 r270 bottom value=1uF
C8 "Capacitor" C0603 52.5,53 r0 top value=1uF
C9 "Capacitor" C0603 71.125,53 r0 top value=1uF
C11 "" C0603 18.33,55.7 r180 top value="100nF, 50V"
C12 "Capacitor" C0402 7.65,51.223 r0 top value=10nF
C13 "Capacitor" C0402 74.225,50.075 r90 top value=100nF
C14 "Capacitor" C0402 70.7,50.05 r90 top value=100nF
C15 "Capacitor" C0402 71.625,50.05 r90 top value=100nF
C16 "Capacitor" C0402 72.775,50.05 r90 top value=100nF
C17 "" C0402 10.8,49.075 r0 bottom value=100nF
C18 "Capacitor" C0603 5.3,54.912 r0 top value=2.2uF
C19 "Capacitor" C0402 5.55,56.062 r0 top value=100nF
C20 "Capacitor" C0603 68.55,48.05 r180 top value=2.2uF
C21 "Capacitor" C0402 75.7,47.7 r0 top value=100nF
C22 "Capacitor" C0402 67.2,46.475 r180 top value=100nF
C23 "Capacitor" C0402 75.7,45.75 r0 top value=100nF
C24 "Capacitor" C0402 67.2,45.275 r180 top value=100nF
C25 "Capacitor" C0402 69.525,44.825 r90 top value=100nF
C26 "Capacitor" C0402 2.325,52.637 r90 top value=100nF
C27 "Capacitor" C0603 1.15,52.637 r90 top value=10uF
C28 "Capacitor" C0402 75.8,43.85 r0 top value=100nF
C29 "Capacitor" C0402 67.575,43.375 r270 top value=100nF
C30 "Capacitor" C0603 71.125,43.55 r180 top value=2.2uF
C31 "Capacitor" C0402 69.9,40.575 r270 top value=100nF
C32 "Capacitor" C0402 70.825,40.575 r270 top value=100nF
C33 "Capacitor" C0402 71.75,40.575 r270 top value=100nF
C34 "" C0402 38.2,39.275 r0 top value=2.2uF
C35 "" C0402 39.925,39.275 r180 top value=100pF
C36 "" C0402 38.2,38.35 r0 top value=2.2uF
C37 "Capacitor" C0603 72.325,36.575 r0 top value=2.2uF
C38 "" C0603 48.3,36 r270 top value=1uF
C39 "" C0402 47.15,35.675 r90 top value=100nF
C40 "Capacitor" C0402 72.325,35.4 r0 top value=100nF
C41 "Capacitor" C0402 51.975,35.075 r0 top value=0.5pF
C42 "Capacitor" C0402 47.05,32.925 r180 top value=100nF
C43 "" C0402 49.475,31.575 r270 top value=100nF
C44 "Capacitor" C0402 51.975,31.575 r180 top value=0.5pF
C45 "Capacitor" C0402 53.1,30.325 r270 top value=1.3pF
C46 "Capacitor" C0402 53.1,28.7 r90 top value=1.3pF
C47 "Capacitor" C0402 92.375,28.525 r90 top value=100pF
C48 "" C0402 43.475,25.95 r90 top value=2.2uF
C49 "" C0402 44.425,25.95 r90 top value=2.2uF
C50 "Capacitor" C0402 36.2,23.25 r90 top value=10uF
C51 "" C0402 27.375,25.85 r90 top value=100nF
C52 "Capacitor" C0603 92.775,24.65 r90 top value=1uF
C53 "Capacitor" C0603 98.2,24.425 r90 top value=1uF
C54 "" C0603 56.55,22.75 r270 top value=4.7uF
C55 "" C0402 41,21.35 r180 top value=100nF
C56 "" C0402 56.3,21.125 r0 top value=100nF
C57 "" C0402 34.225,20.225 r0 top value=100nF
C58 "Capacitor" C0805 56.425,18.9 r90 top value=10uF
C59 "" C0402 35.075,17.775 r90 top value=100nF
C60 "" C0402 37.225,16.05 r90 top value=100nF
C61 "Capacitor" C0603 26.95,13.35 r180 top value=10uF
C62 "Capacitor" C0603 34.575,12.55 r270 top value=4.7uF
C63 "" C0402 26.95,12.125 r0 top value=100nF
C64 "" C0402 33.025,11.85 r180 top value=100nF
C65 "" C0402 25.15,10.6 r270 top value=100nF
C66 "" C0402 14,10.525 r270 top value=100nF
C67 "" C0402 19.75,10.525 r270 top value=100nF
C68 "" C0402 34.475,10.325 r270 top value=100nF
C69 "Capacitor" C0402 29.25,10.05 r180 top value=220nF
C70 "Capacitor" C0603_H0P8 25.9,5.95 r180 top value=2.2uF
C71 "" C0402 25.575,4.775 r0 top value=100nF
C72 "" C0402 34.825,2.475 r270 top value=100nF
C73 "Capacitor" C0603 35.925,2.15 r90 top value=4.7uF
C74 "" C0402 60.975,51.575 r90 bottom value=100nF
C75 "" C0402 7.95,51.41 r90 bottom value=100pF
C76 "" C0402 41,50.775 r180 bottom value=100nF
C77 "Capacitor" C0402 78.05,48.725 r0 bottom value=100nF
C78 "" C0402 44.15,47.6 r270 bottom value=100nF
C79 "Capacitor" C0402 80.075,47.525 r0 bottom value=100nF
C80 "Capacitor" C0402 82.445,47.52 r180 bottom value=100nF
C81 "Capacitor" C0402 63.675,46.775 r180 bottom value=20pF
C82 "" C0402 38.85,45.6 r90 bottom value=100nF
C83 "Capacitor" C0603 65.075,45.075 r0 bottom value=2.2uF
C84 "Capacitor" C0603 65.075,42.175 r0 bottom value=1uF
C85 "Capacitor" C0402 78.05,41.475 r0 bottom value=100nF
C86 "Capacitor" C0603 65.075,40.8 r0 bottom value=4.7uF
C87 "Capacitor" C0402 78.05,40.525 r0 bottom value=100nF
C88 "Capacitor" C0402 40.525,38.8 r270 bottom value=10uF
C89 "Capacitor" C0402 39.6,38.8 r270 bottom value=10uF
C90 "" C0402 38.65,38.8 r270 bottom value=100nF
C91 "" C0402 37.35,38.8 r270 bottom value=100nF
C92 "" C0402 44.388,38 r180 bottom value=100nF
C93 "" C0402 41.3,37.475 r0 bottom value=100nF
C94 "" C0603 46.8,35.925 r270 bottom value=1uF
C95 "" C0402 45.65,36.125 r90 bottom value=100nF
C96 "Capacitor" C0402 37.575,36.1 r180 bottom value=10uF
C97 "" C0402 37.575,35.15 r180 bottom value=100nF
C98 "" C0402 37.575,34.25 r180 bottom value=100nF
C99 "" C0402 46.675,32.75 r180 bottom value=100nF
C100 "" C0402 37.575,32.55 r180 bottom value=100nF
C101 "" C0402 37.6,30.75 r180 bottom value=100nF
C102 "" C0603 47,30.275 r0 bottom value=1uF
C103 "" C0402 46.675,28.9 r180 bottom value=100nF
C104 "Capacitor" C0402 81.925,27.65 r180 bottom value=100nF
C105 "Capacitor" C0402 79.575,26.55 r270 bottom value=10nF
C106 "Capacitor" C0603 82.175,26.5 r180 bottom value=1uF
C107 "" C0402 45.35,25.95 r90 bottom value=100nF
C108 "" C0603 43.725,26.125 r180 bottom value=4.7uF
C109 "" C0402 42.025,25.95 r90 bottom value=100nF
C110 "" C0402 40.6,25.95 r90 bottom value=100nF
C111 "" C0402 38.6,25.95 r90 bottom value=100nF
C112 "Capacitor" C0402 82.05,20.525 r180 bottom value=100nF
C113 "Capacitor" C0603 82.375,19 r180 bottom value=1uF
C114 "" C0402 44.15,16.6 r270 bottom value=100nF
C115 "Capacitor" C0402 11.375,16.9 r180 bottom value=10uF
C116 "Capacitor" C0603 70.225,14.22 r270 bottom value=10uF
C117 "Capacitor" C0603 59.875,14.6 r0 bottom value=10uF
C118 "" C0603 8.275,11.925 r0 bottom value=1uF
C119 "Capacitor" C0402 41.725,12.025 r0 bottom value=100nF
C120 "Capacitor" C0402 21.25,55.85 r180 top value=330pF
C121 "Capacitor" C0402 17.2,54.05 r0 top value=330pF
C122 "Capacitor" C0201_H0P3 10.35,66.6 r180 top value="3.3 pF"
C123 "Capacitor" C0201_H0P3 10.35,65.775 r180 top value="3.3 pF"
C124 "Capacitor" C0201_H0P3 10.35,64.975 r0 top value="3.3 pF"
C125 "" C0402 36.2,25.55 r90 top value=100nF
C126 "" C0402 63.75,67.2 r90 bottom value=100nF
C127 "" C0402 59.849,40.452 r270 bottom value=100nF
CN1 "USB_TYPE_C_Receptacle_317JD24BZTF3K3C3" CON_USB-TYPEC_COXOC_317JD24BZTF3K3C3 19.53,70 r180 top value=317JD24BZTF3K3C3
CN2 "Socket 10X2 STMod+" CON_SAMTEC_SQT-110-01-F-D-RA__STMOD+ 44.05,61.01 r180 top
CN3 "Socket 10X2 STMod+" CON_SAMTEC_SQT-110-01-F-D-RA__STMOD+ 80.525,61.05 r180 top
CN4 "Socket 6X2 PMOD" CON_SAMTEC_SSW-106-02-F-D-RA__PMOD 88.408,48.86 r90 top
CN5 "Header 4x1" CON_SAMTEC_TSW-104-07-G-S 15.928,46.29 r90 top
CN6 "Header 4x1" CON_SAMTEC_TSW-104-07-G-S 56.025,43.875 r90 top
CN7 "" CON_SAMTEC_CLM-120-02-L-D_Reverse-to-Camera 16.885,19.535 r0 top value=CLM-120-02-L-D
CN8 "USB_uB_105017.0001" CON_USBMICROB_MOLEX_105017-0001_H2P90 99.975,30.9 r90 top value=USB_uB_105017-0001
CN9 "Header 7x2" CON_STDC14_Receiver_MEDIUM_WITH_MIPI10_3D 64,27.825 r180 top value="MIPI10 on STDC14 footprint"
CN10 "" CON_TAG-C_TC2050-IDC-NL 64,18.625 r180 top value=TC2050-IDC-NL
CN11 "Header 4x1" CON_SAMTEC_TSW-104-07-G-S 95.4,14.35 r90 top
CN12 "USB_uAB_10104111-0001LF" CON_USBMICROAB_FCI_10104111-0001LF 0,54.725 r90 bottom value=10104111-0001LF
CN13 "Socket 10x1" CON_SAMTEC_SSM-110-L-SV 55.614,55.57 r0 bottom locked value=SSM-110-L-SV
CN14 "Socket 8x1" CON_SAMTEC_SSM-108-L-SV 31.23,55.57 r0 bottom locked value=SSM-108-L-SV
CN15 "" BAT_HARWIN_S8411-45R_SMD_2P 28.335,32.5 r90 bottom value="CR1220 holder"
CN16 "Socket 6x1" CON_SAMTEC_SSM-106-L-SV 28.69,7.31 r180 bottom locked value=SSM-106-L-SV
CN17 "Socket 8x1" CON_SAMTEC_SSM-108-L-SV 49.01,7.31 r180 bottom locked value=SSM-108-L-SV
D2 "BAT60JFILM" DIO_SOD323 81.675,16.05 r90 bottom
D3 "BAT60JFILM" DIO_SOD323 79.625,16.05 r90 bottom
D4 "BAT60JFILM" DIO_SOD323 77.55,16.05 r90 bottom
H1 "" PTH_M1261-3005-N_3P5X6_M3_H14 95,65 r180 bottom
H3 "" PTH_M1261-3005-N_3P5X6_M3_H14 5,5 r180 bottom
H4 "" PTH_M1261-3005-N_3P5X6_M3_H14 95,5 r180 bottom
HW1 "Comment" LOGO_ETIQUETTE 94.3,36.825 r270 bottom
JP1 "Jumper_Header 2x1" CON_SAMTEC_TSW-102-07-G-S 81.9,49.525 r180 top value="Shunt not fitted"
JP3 "Jumper_Header 2x1" CON_SAMTEC_TSW-102-07-G-S 51.675,26.35 r0 top value="Shunt for curent measurement."
JP4 "Jumper_Header 4x2" CON_SAMTEC_TSW-104-07-X-D 65.135,3.66 r180 top value=Jumper_Header_4x2
L1 "Inductor" L0805_H0P9 38.975,40.75 r0 top value=2.2uH
LD1 "" LED_0603_GREEN 28.225,68.125 r270 top value=GREEN
LD2 "​reference from jiubaba" LED_0603_SMD-B_BLUE_H0P4 57.375,54.1 r270 top value=BLUE
LD3 "LD_BICOLOR_CMS" LED_BI-GR_HSMF-A201-A00J1 88.675,38.525 r90 top
LD4 "LED_red" LED_0603_RED 94.675,21.825 r180 top value=RED
LD5 "" LED_0603_OSRAM_LG-Q396-PS-35_GREEN_1A2K_H0P4 57.15,5.075 r90 top value=GREEN
LD6 "LED_red" LED_0603_VISHAY_VLMS1300-GS08_RED_1A2K_H0P8 35.85,5.025 r90 top value=RED
LD7 "" LED_0603_OSRAM_LG-Q396-PS-35_GREEN_1A2K_H0P4 37.35,5.025 r90 top value=GREEN
M1 "EMW3080(BP)" MOD_WIFI_MXCHIP_EMW3080-BP 81.28,33.147 r180 top
MIRE1 "Comment" MIRE_PLACE_SMD_0P8MM 12.825,60.325 r0 top
MIRE2 "Comment" MIRE_PLACE_SMD_0P8MM 96.925,58.825 r0 top
MIRE3 "Comment" MIRE_PLACE_SMD_0P8MM 10.6,2.4 r0 top
MIRE4 "Comment" MIRE_PLACE_SMD_0P8MM 12.825,60.85 r180 bottom
MIRE5 "Comment" MIRE_PLACE_SMD_0P8MM 95.725,58.825 r180 bottom
MIRE6 "Comment" MIRE_PLACE_SMD_0P8MM 97.975,9.5 r180 bottom
Q1 "" NPN_SOT23 28.225,64.525 r0 top value=9013-SOT23
Q2 "STL40DN3LLH5" PowerFLAT_5x6 25.5,43.5 r90 top
Q3 "DTC043ZEBTL" NPN_SOT416-FL_EMT3F_1616_SC89 57.375,51.7 r0 top
Q4 "BSN20" MOS_SOT23 8.775,30.9 r0 top value=FDV303N
Q5 "BSN20" MOS_SOT23 8.8,24.175 r0 top value=FDV303N
Q6 "STL40DN3LLH5" PowerFLAT_5x6 23.85,36.1 r90 top
R1 "" R0603 29.575,68.3 r90 top value=510R
R2 "" R0603 28.25,61.775 r180 top value=22K
R3 "" R0402 1,61.3 r90 top value=10K
R4 "" R0603 28.25,60.4 r180 top value=47K
R5 "" R0603 26.804,58.275 r270 top value=330K
R6 "" R0603 29.604,58.275 r90 top value=49K9
R7 "" R0603 26.4,52.6 r270 top value=10K
R8 "Resistor" R0402 26.375,54.625 r90 top value=2K4
R9 "Resistor" R0402 58.75,54.3 r90 top value=510R
R10 "" R0402 54.225,52.825 r270 top value=10K
R11 "" R0402 72.85,52.825 r270 top value=10K
R12 "" R0603 42.675,52.1 r90 top value=10K
R13 "Resistor" R0805_H0P5 22.8,48.35 r0 top value=0R047
R14 "" R0603 47.55,46.6 r180 top value=0R
R15 "" R0603 47.55,45.2 r180 top value=10K
R16 "Resistor" R0402 85.35,39.275 r180 top value=330R
R17 "Resistor" R0402 85.35,37.775 r180 top value=330R
R18 "Resistor" R0402 60.925,37.3 r90 top value=47R
R19 "Resistor" R0402 62.225,37.3 r270 top value=47R
R20 "Resistor" R0402 65.875,37.3 r90 top value=47R
R21 "" R0402 50.65,36.25 r90 top value=0R
R22 "Resistor" R0402 63.5,34.425 r90 top value=47R
R23 "Resistor" R0402 64.525,34.425 r90 top value=47R
R24 "Resistor" R0402 68.475,34.425 r90 top value=47R
R25 "Resistor" R0402 69.6,34.425 r270 top value=100R
R26 "Resistor" R0603 11.375,30.9 r270 top value=0R
R27 "Resistor" R0603 30.675,30.75 r0 top value=3K3
R28 "Resistor" R0603 30.675,29.325 r0 top value=3K3
R29 "" R0402 8.775,28.4 r180 top value=4K7
R30 "Resistor" R0603 11.375,24.175 r270 top value=0R
R31 "Resistor" R0402 98.55,22.65 r180 top value=10K
R32 "" R0603 12.85,22.05 r180 top value=10K
R33 "Resistor" R0402 96.9,21.825 r0 top value=1K
R34 "" R0402 8.8,21.675 r180 top value=4K7
R35 "" R0603 47.85,20.075 r90 top value=10K
R36 "Resistor" R0402 95.625,20.4 r0 top value=100K
R37 "" R0603 47.45,18.025 r0 top value=10K
R38 "" R0603 47.45,16.6 r180 top value=0R
R39 "" R0603 46.575,13.55 r180 top value=200R
R40 "" R0603 46.575,12.125 r180 top value=20K
R41 "" R0402 35.85,7.3 r90 top value=360R
R42 "" R0402 37.35,7.3 r90 top value=270R
R43 "Resistor" R0402 30.275,5.45 r90 top value=10K
R44 "" R0402 57.15,2.85 r270 top value=620R
R46 "Resistor" R0402 5.875,56.41 r270 bottom value=100K
R47 "" R0402 61.975,51.575 r270 bottom value=0R
R48 "" R0402 56.875,51.55 r270 bottom value=0R
R49 "Resistor" R0402 65.4,46.775 r180 bottom value=100R
R50 "Resistor" R0402 79.325,46.1 r180 bottom value=100R
R51 "Resistor" R0402 65.4,43.825 r0 bottom value=3K
R52 "Resistor" R0402 78.05,43.675 r180 bottom value=10K
R53 "Resistor" R0402 82.725,43.225 r90 bottom value=10K
R54 "Resistor" R0402 75.55,39 r270 bottom value=4K7
R55 "Resistor" R0402 74.475,39 r270 bottom value=4K7
R56 "Resistor" R0402 73.4,39 r90 bottom value=4K7
R57 "Resistor" R0402 72.35,39 r90 bottom value=2K7
R58 "Resistor" R0402 62.625,30.975 r180 bottom value=100R
R59 "Resistor" R0603 47.975,25.625 r270 bottom value=3K3
R60 "Resistor" R0603 46.525,25.625 r270 bottom value=3K3
R61 "" R0603 8.275,21.35 r0 bottom value=150R
R62 "Resistor" R0603 10.925,18.825 r270 bottom value=120R
R63 "Resistor" R0402 57.9,3.2 r270 bottom value=1K
R64 "" R0603 80.9,40.325 r270 bottom value=10K
R65 "" R0603 82.575,40.35 r270 bottom value=10K
R66 "Resistor" R0402 63.25,42.675 r90 bottom value=10K
SB2 "" SOLDER-BRIDGE_R0603-0R 47.55,45.2 r0 bottom
SB3 "" SOLDER-BRIDGE_R0603-0R 48.3,36 r270 bottom
SB4 "" SOLDER-BRIDGE_R0603-0R 58.5,34.625 r0 bottom
SB5 "" SOLDER-BRIDGE_R0603-0R 55.825,32.65 r0 bottom
SB6 "" SOLDER-BRIDGE_R0603-0R 44.35,29.7 r90 bottom
SB7 "" SOLDER-BRIDGE_R0603-0R 42.925,29.7 r90 bottom
SB8 "" SOLDER-BRIDGE_R0603-0R 47.475,18.025 r0 bottom
SB9 "" SOLDER-BRIDGE_R0603-0R 10.925,14.55 r270 bottom
SB10 "" SOLDER-BRIDGE_R0603-0R 25.225,11.85 r270 bottom
SB11 "" SOLDER-BRIDGE_R0603-0R 23.775,11.85 r270 bottom
SB12 "" SOLDER-BRIDGE_R0603-0R 22.35,11.85 r270 bottom
SB13 "" SOLDER-BRIDGE_R0603-0R 20.925,11.85 r270 bottom
SB15 "" SOLDER-BRIDGE_R0603-0R 19.325,43.925 r90 top
SB16 "" SOLDER-BRIDGE_R0603-0R 27.755,48.869 r0 top
SB17 "" SOLDER-BRIDGE_R0603-0R 23.525,25.011 r270 top
SW1 "CJS-1200A1" SWI_CJS-1200A1 52.4,16.95 r0 top
SW2 "SWITCH_2WAY" SWI_MULTICOMP_MCDHN-02F-V_4P 80.45,40.65 r0 top value=MCDHN-02F-V
SW3 "CJS-1200A1" SWI_CJS-1200A1 10.75,47.125 r180 top
TP1 "" TP_SMD_1MM 42,43.375 r90 top value=VPP
TP2 "" TP_SMD_1MM 55.85,37.375 r90 top value=OPAMP1_VINM
TP3 "" TP_SMD_1MM 55.85,35 r180 top value=OPAMP2_VINM
TP4 "Test Point" TP_SMD_1MM 24,29.035 r90 top
TP5 "" TP_PTH_1MM_2MM 56.025,26.35 r90 top
TP6 "Test Point" TP_SMD_1MM 24,18.975 r90 top
TP7 "Test Point" TP_SMD_1MM 5.1,19.275 r90 top
TP8 "Test Point" TP_SMD_1MM 24,16.95 r90 top
TP9 "Test Point" TP_SMD_1MM 24,14.575 r90 top
TP10 "Test Point" TP_SMD_1MM 24,12.65 r90 top
TP11 "Test Point" TP_SMD_1MM 5.1,12.025 r90 top
TP12 "" TP_PTH_1MM_2MM 2.125,10.025 r90 top value=2V8
U1 "STM32WB5MMGH6TR" MOD_DORY_STM_86P_7P3X11_H1P342 5.5,64.175 r0 top
U2 "ESD-TRANSIL" ESD_QFN1610_2N_1K_2A 21.5,57.8 r0 top value=ESDA25P35-1U1M
U3 "STG3692QTR" ICC_UFQFN16-EPAD_2P6X1P8_P040 53.425,55.125 r0 top
U4 "STG3692QTR" ICC_UFQFN16-EPAD_2P6X1P8_P040 72.025,55.125 r0 top
U5 "USBLC6-2SC6" ESD_SOT23-6L 29.1,53.9 r180 top
U6 "MP23DB01MMTR" MIC_STM_MP23DB01MMTR 61.812,68.116 r0 bottom value=MP23DB01HPTR
U7 "MP23DB01MMTR" MIC_STM_MP23DB01MMTR 61.812,39.571 r180 bottom value=MP23DB01HPTR
U8 "TCPP03-M20" ICC_QFN20-EPAD_4X4_P050 20.75,52.125 r90 top
U9 "" ICC_BGA24_5X5-BALL-ARRAY_6X8_P1 42,47.6 r270 top value=MX25LM51245GXDI00
U10 "LD3985M33R" REG_SOT23-5L 4.9,52.162 r270 top
U11 "ESDALC6V1W5" ESD_SOT323-5L 61.575,34.825 r180 top
U12 "ESDALC6V1W5" ESD_SOT323-5L 66.525,34.825 r180 top
U13 "STM32U585AII6QU" ICC_UFBGA169_7X7_P050 41.829,32.6 r180 top
U14 "ECMF02-2AMX6" ESD_QFN-6L_1P7X1P5_P050 92.95,31.975 r180 top
U15 "ESD-TRANSIL" ESD_QFN1610_2N_1K_2A 93.775,28.55 r270 top value=ESDA7P120-1U1M
U16 "STSAFA110S8" ICC_SO8_5X4_P127 32.175,24.875 r90 top
U17 "VEML6030" ICC_VISHAY_VEML6030_2X2_P065 25.605,25.875 r90 top
U18 "STMPS2151STR" MOS_SOT23-5L 95.45,24.175 r270 top
U19 "ST1L05APU33R" ICC_DFN6-EPAD_3X3_P095 53.625,21.125 r90 top
U20 "APS6408L-xOB" ICC_MINI-BGA24_6X8_P1 42,17.6 r270 top value=APS6408L-3OB-BA
U21 "ISM330DHCX" ICC_LGA14_3X2P5_P050 32.875,17.825 r90 top
U22 "M24128-DFMC6TP" ICC_DFN8-EPAD_2X3_P050 27.606,17.647 r180 top value=M24256-DFMC6TG
U23 "" ESD_ST0201 49.6,13.375 r180 top value=ESDALC6V1-1U2
U24 "" ESD_ST0201 44.475,12.125 r180 top value=ESDALC6V1-1U2
U25 "IIS2MDCTR" ICC_LGA12_2X2_P050_H0P7 26.95,10.3 r90 top
U26 "LPS22HH" ICC_HLGA10_2X2_P050 32.525,10.075 r270 top
U27 "VL53L5CAV0GC" ICC_LGA16_6P4X3_P075_H1P5 31.025,2.925 r180 top value=VL53L5CAV0GC/1
U28 "HTS221" ICC_HLGA6_2X2_P075-1 24.55,2.925 r270 top
U29 "ESD-TRANSIL" ESD_QFN1610_2N_1K_2A 58.875,3.025 r90 top value=ESDA7P120-1U1M
U30 "ECMF02-2AMX6" ESD_QFN-6L_1P7X1P5_P050 7.35,54.175 r270 bottom
U31 "ESD-TRANSIL" ESD_QFN2_1P6X1_P125 6.575,51.41 r270 bottom value=ESDA7P60-1U1M
U32 "ST-LINKV3E_SWD" ICC_UFBGA201_176+25_10X10_P065 71.8,45.475 r180 bottom
U33 "ESD-TRANSIL" ESD_ST0201 58,47.4 r270 bottom value=ESDALC6V1-1U2
U34 "ESD-TRANSIL" ESD_ST0201 58,42.3 r270 bottom value=ESDALC6V1-1U2
U35 "LD3985M33R" REG_SOT23-5L 80.525,23.6 r180 bottom
U36 "" REG_SOT223-TAB 5.8,16.85 r270 bottom value=LD1117STR
U37 "APS1604M-3SQR-SN" ICC_SO8_5X4_P127 39.809,15.253 r90 bottom
U38 "LD1117S50TR" REG_SOT223-TAB 65.25,12.3 r90 bottom
U39 "ESD-TRANSIL" ESD_ST0201 12.225,49.438 r90 bottom value=ESDALC6V1-1U2
X1 "XTAL_4_PINS" CRY_NX2016SA_4P 51.975,33.325 r90 top value="NX2016SA 16MHz"
X2 "XTAL_2_PINS" CRY_NX1610SE_2P 51.7,29.5 r270 top value="NX1610SE 32.768kHz"
X3 "OSCILLATOR_4_PINS" OSC_NDK_NZ2520SB_4P 81.9,45.475 r180 bottom value="NZ2520SH 25MHz"

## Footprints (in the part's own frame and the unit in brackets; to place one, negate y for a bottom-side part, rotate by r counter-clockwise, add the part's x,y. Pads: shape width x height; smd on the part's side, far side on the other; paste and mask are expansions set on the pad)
BAT_HARWIN_S8411-45R_SMD_2P [mm] "CR1220 HOLDER"
  rect 4.5x2.3 smd mask+0.05: 1(8.2,0) 2(-8.2,0)
  round 0 hole 1.1 unplated mask+0.05: NPTH1(-3.5,0)
  round 0 hole 1.3 unplated mask+0.05: NPTH2(3.95,0)
  silkscreen extent -9.03,-7.5 9.62,7.5, body extent -8.93,-7.5 9.88,7.5, height 4.3
C0201_H0P3 [mm] "MCD-00699"
  rect 0.4x0.5 smd mask+0.05: 1(-0.3,0) 2(0.3,0)
  body extent -0.32,-0.17 0.32,0.17, height 0.33
C0402 [mm]
  rect 0.51x0.56 smd mask+0.05: 1(-0.45,0) 2(0.45,0)
  silkscreen extent 0,-0.3 0,0.3, body extent -0.5,-0.3 0.5,0.3, height 0.4
C0603 [mm]
  rect 0.64x0.89 smd mask+0.05: 1(-0.7,0) 2(0.7,0)
  silkscreen extent -1.05,-0.55 1.02,0.55, body extent -0.9,-0.5 0.9,0.5, height 1.4
C0603_H0P8 [mm] "MCD-01540"
  rect 0.64x0.89 smd mask+0.05: 1(-0.7,0) 2(0.7,0)
  silkscreen extent -0.9,-0.55 0.9,0.55, body extent -0.9,-0.5 0.9,0.5, height 1
C0805 [mm]
  rect 0.9x1.4 smd mask+0.05: 1(-0.85,0) 2(0.85,0)
  silkscreen extent -1.3,-0.77 1.3,0.77, body extent -1.1,-0.7 1.1,0.7, height 1.35
CON_SAMTEC_CLM-120-02-L-D_Reverse-to-Camera [mm] "not in line with Samtec spec"
  rect 1.85x0.7 smd mask+0.05: 1(-1.275,9.5) 2(1.275,9.5) 3(-1.275,8.5) 4(1.275,8.5) 5(-1.275,7.5) 6(1.275,7.5) 7(-1.275,6.5) 8(1.275,6.5) 9(-1.275,5.5) 10(1.275,5.5) 11(-1.275,4.5) 12(1.275,4.5) 13(-1.275,3.5) 14(1.275,3.5) 15(-1.275,2.5) 16(1.275,2.5) 17(-1.275,1.5) 18(1.275,1.5) 19(-1.275,0.5) 20(1.275,0.5) 21(-1.275,-0.5) 22(1.275,-0.5) 23(-1.275,-1.5) 24(1.275,-1.5) 25(-1.275,-2.5) 26(1.275,-2.5) 27(-1.275,-3.5) 28(1.275,-3.5) 29(-1.275,-4.5) 30(1.275,-4.5) 31(-1.275,-5.5) 32(1.275,-5.5) 33(-1.275,-6.5) 34(1.275,-6.5) 35(-1.275,-7.5) 36(1.275,-7.5) 37(-1.275,-8.5) 38(1.275,-8.5) 39(-1.275,-9.5) 40(1.275,-9.5)
  round 6 hole 3.2 mask+0.1: 41(0,15.27) 42(0,-15.27)
  silkscreen extent -16.5,-19 6,21, body extent -16.5,-19 6,21, height 5.69
CON_SAMTEC_SQT-110-01-F-D-RA__STMOD+ [mm] "SQT-110-01-F-D-RA (connecteur SAMTEC pour interface STMod+ femelle coté Host) Pinning adapté non conforme SAMTEC."
  rect 1.7x1.7 hole 0.9 mask+0.05: 1(9,1)
  round 1.7 hole 0.9 mask+0.05: 2(7,1) 3(5,1) 4(3,1) 5(1,1) 6(-1,1) 7(-3,1) 8(-5,1) 9(-7,1) 10(-9,1) 11(9,-1) 12(7,-1) 13(5,-1) 14(3,-1) 15(1,-1) 16(-1,-1) 17(-3,-1) 18(-5,-1) 19(-7,-1) 20(-9,-1)
  silkscreen extent -10.15,-8.62 10.15,0.07, body extent -10.15,-8.65 10.15,1.22, height 4
CON_SAMTEC_SSM-106-L-SV [mm] "MCD-02346"
  rect 1.02x1.905 smd mask+0.05: 1(-6.35,-1.602) 2(-3.81,1.603) 3(-1.27,-1.602) 4(1.27,1.603) 5(3.81,-1.602) 6(6.35,1.603)
  silkscreen extent -7.62,-1.27 7.62,1.27, body extent -7.62,-2.29 7.62,2.29, height 7.37
CON_SAMTEC_SSM-108-L-SV [mm] "MCD-02345"
  rect 1.02x1.905 smd mask+0.05: 1(-8.89,-1.602) 2(-6.35,1.603) 3(-3.81,-1.602) 4(-1.27,1.603) 5(1.27,-1.602) 6(3.81,1.603) 7(6.35,-1.602) 8(8.89,1.603)
  silkscreen extent -10.16,-1.27 10.16,1.27, body extent -10.16,-2.29 10.16,2.29, height 7.37
CON_SAMTEC_SSM-110-L-SV [mm] "MCD-02342"
  rect 1.02x1.905 smd mask+0.05: 1(-11.43,-1.602) 2(-8.89,1.603) 3(-6.35,-1.602) 4(-3.81,1.603) 5(-1.27,-1.602) 6(1.27,1.603) 7(3.81,-1.602) 8(6.35,1.603) 9(8.89,-1.602) 10(11.43,1.603)
  silkscreen extent -12.7,-1.27 12.7,1.27, body extent -12.7,-2.29 12.7,2.29, height 7.49
CON_SAMTEC_SSW-106-02-F-D-RA__PMOD [mm] "SSW-106-02-F-D-RA (connecteur SAMTEC pour interface PMOD femelle coté Host) Pinning adapté non conforme SAMTEC."
  rect 1.9x1.9 hole 1.1 mask+0.05: 1(6.35,1.27)
  round 1.9 hole 1.1 mask+0.05: 2(3.81,1.27) 3(1.27,1.27) 4(-1.27,1.27) 5(-3.81,1.27) 6(-6.35,1.27) 7(6.35,-1.27) 8(3.81,-1.27) 9(1.27,-1.27) 10(-1.27,-1.27) 11(-3.81,-1.27) 12(-6.35,-1.27)
  silkscreen extent -7.88,-11.3 7.88,0.23, body extent -7.87,-11.31 7.87,1.47, height 5.21
CON_SAMTEC_TSW-102-07-G-S [mm]
  rect 1.85x1.85 / inner round 1.85 / far side rect 1.85x1.85 hole 1 mask+0.05: 1(-1.27,0)
  round 1.85 hole 1 mask+0.05: 2(1.27,0)
  silkscreen extent -2.58,-1.3 2.58,1.3, body extent -2.67,-1.3 2.58,1.3, height 8.38
CON_SAMTEC_TSW-104-07-G-S [mm]
  rect 1.85x1.85 / inner round 1.85 / far side rect 1.85x1.85 hole 1 mask+0.05: 1(-3.81,0)
  round 1.85 hole 1 mask+0.05: 2(-1.27,0) 3(1.27,0) 4(3.81,0)
  silkscreen extent -5.12,-1.3 5.12,1.3, body extent -5.21,-1.37 5.18,1.37, height 8.38
CON_SAMTEC_TSW-104-07-X-D [mm]
  rect 1.85x1.85 / inner round 1.85 / far side rect 1.85x1.85 hole 1 mask+0.05: 1(-3.81,-1.27)
  round 1.85 hole 1 mask+0.05: 2(-3.81,1.27) 3(-1.27,-1.27) 4(-1.27,1.27) 5(1.27,-1.27) 6(1.27,1.27) 7(3.81,-1.27) 8(3.81,1.27)
  silkscreen extent -5.08,-2.54 5.08,2.54, body extent -5.08,-2.54 5.08,2.54, height 8.38
CON_STDC14_Receiver_MEDIUM_WITH_MIPI10_3D [mm] "compatible with FTSH-105-01-L-DV,-K and FTSH-107-01-L-DV,-K,-A,-P,-ES"
  round 0 hole 1.19 unplated mask+0.05: 0(-5.445,0) 0(5.445,0)
  round 0 hole 0.97 unplated mask+0.05: 0(-3.175,0) 0(3.175,0)
  rect 0.74x2.79 smd mask+0.05: 1(-3.81,-2.032) 2(-3.81,2.032) 3(-2.54,-2.032) 4(-2.54,2.032) 5(-1.27,-2.032) 6(-1.27,2.032) 7(0,-2.032) 8(0,2.032) 9(1.27,-2.032) 10(1.27,2.032) 11(2.54,-2.032) 12(2.54,2.032) 13(3.81,-2.032) 14(3.81,2.032)
  silkscreen extent -6.3,-4.38 6.3,3.6, body extent -6.3,-2.92 6.3,2.92, height 6.6
CON_TAG-C_TC2050-IDC-NL [mm]
  round 0.9 smd paste+0 mask+0.05: 1(-2.54,-0.635) 2(-1.27,-0.635) 3(0,-0.635) 4(1.27,-0.635) 5(2.54,-0.635) 6(2.54,0.635) 7(1.27,0.635) 8(0,0.635) 9(-1.27,0.635) 10(-2.54,0.635)
  round 0 hole 1.1 unplated mask+0.05: 11(-3.81,0) 12(3.81,-1.015) 13(3.81,1.015)
  Multi-Layer keep-out circle w0.01: c3.81,-1.015 r0.75
  Multi-Layer keep-out circle w0.01: c3.81,1.015 r0.75
  Multi-Layer keep-out circle w0.01: c-3.81,0 r0.75
  silkscreen extent -6.22,-3.4 6.22,3.33, body extent -6.28,-3.46 6.28,3.39, height 13
CON_USB-TYPEC_COXOC_317JD24BZTF3K3C3 [mm]
  rect 0.3x1.2 smd mask+0.05: A1(-2.75,10.58) A2(-2.25,10.58) A3(-1.75,10.58) A4(-1.25,10.58) A5(-0.75,10.58) A6(-0.25,10.58) A7(0.25,10.58) A8(0.75,10.58) A9(1.25,10.58) A10(1.75,10.58) A11(2.25,10.58) A12(2.75,10.58)
  round 0.6 hole 0.4 mask+0.05: B1(2,9.33) B1(2.8,9.33) B2(2.4,8.62) B3(1.6,8.62) B4(1.2,9.33) B5(0.8,8.62) B6(0.4,9.33) B7(-0.4,9.33) B8(-0.8,8.62) B9(-1.2,9.33) B10(-1.6,8.62) B11(-2.4,8.62) B12(-2.8,9.33) B12(-2,9.33)
  oval 1.15x1.55 hole 0.45 slot 0.85 at 90 deg mask+0.05: SH1(-4.27,8.18) SH2(-4.27,3.45) SH3(4.27,8.18) SH4(4.27,3.45)
  silkscreen extent -4.38,-0.95 4.38,10.38, body extent -4.38,-0.95 4.38,10.84, height 3.03
CON_USBMICROAB_FCI_10104111-0001LF [mm]
  rect 0.4x1.4 smd mask+0.05: 1(-1.3,4.3) 2(-0.65,4.3) 3(0,4.3) 4(0.65,4.3) 5(1.3,4.3)
  rect 1.775x1.9 smd mask+0.05: EXP1(-1.162,1.45) EXP2(1.162,1.45)
  rect 2.3x1.9 smd mask+0.05: SH1(-3.75,1.45) SH2(3.75,1.45)
  silkscreen extent -4.05,-2.95 4.05,4.45, body extent -4.4,-1.3 4.4,4.45, height 3.07
CON_USBMICROB_MOLEX_105017-0001_H2P90 [mm]
  rect 0.4x1.35 smd mask+0.05: 1(-1.3,4.15) 2(-0.65,4.15) 3(0,4.15) 4(0.65,4.15) 5(1.3,4.15)
  round 1.5 hole 0.9 mask+0.05: 6(-2.5,4.15) 7(2.5,4.15)
  oval 1.2x1.9 hole 0.6 slot 1.3 at 90 deg mask+0.05: 8(3.5,1.45) 9(-3.5,1.45)
  rect 1.5x1.9 smd mask+0.05: 10(-1,1.45) 11(1,1.45)
  Top Layer region: 2.3,2.4 3.5,2.4 3.5,0.5 2.3,0.5 2.3,2.4
  Top Layer region: -3.5,2.4 -2.3,2.4 -2.3,0.5 -3.5,0.5 -3.5,2.4
  silkscreen extent -4,-0.7 4,4.6, body extent -4.1,-1.15 4.1,4.66, height 2.9
CRY_NX1610SE_2P [mm] "MCD-02291"
  rect 0.5x1 smd mask+0.05: 1(-0.55,0) 2(0.55,0)
  silkscreen extent -0.13,-0.5 0.13,0.5, body extent -0.8,-0.5 0.8,0.5, height 0.45
CRY_NX2016SA_4P [mm]
  rect 0.85x0.75 smd mask+0.05: 1(-0.675,-0.525) 2(0.675,-0.525) 3(0.675,0.525) 4(-0.675,0.525)
  silkscreen extent -1.22,-1.02 1.05,0.85, body extent -1.05,-0.85 1.05,0.85, height 0.7
DIO_SOD323 [mm]
  rect 1.06x0.54 smd mask+0.05: 1(-1.07,0) 2(1.07,0)
  silkscreen extent -0.9,-0.72 0.9,0.72, body extent -1.3,-0.78 1.3,0.78, height 1.17
ESD_QFN2_1P6X1_P125 [mm]
  rect 0.55x0.8 smd mask+0.05: 1(-0.625,0) 2(0.625,0)
  silkscreen extent -1,-0.55 0.85,0.55, body extent -0.85,-0.55 0.85,0.55, height 0.61
ESD_QFN1610_2N_1K_2A [mm] "DFN, 2-Leads, Body 1.60x1.00mm"
  rect 0.55x0.9 smd mask+0.05: 1(-0.625,0) 2(0.625,0)
  silkscreen extent -1.02,-0.58 0.85,0.58, body extent -0.85,-0.55 0.85,0.55, height 0.6
ESD_QFN-6L_1P7X1P5_P050 [mm]
  rect 0.25x0.6 smd mask+0.05: 1(-0.5,-0.65) 2(0,-0.65) 3(0.5,-0.65) 4(0.5,0.65) 5(0,0.65) 6(-0.5,0.65)
  silkscreen extent -0.9,-0.8 0.9,0.8, body extent -0.9,-0.8 0.9,0.8, height 0.56
ESD_SOT23-6L [mm]
  rect 0.6x1.2 smd mask+0.05: 1(-0.95,-1.15) 2(0,-1.15) 3(0.95,-1.15) 4(0.95,1.15) 5(0,1.15) 6(-0.95,1.15)
  silkscreen extent -1.53,-0.87 1.53,0.87, body extent -1.52,-1.5 1.52,1.5, height 1.45
ESD_SOT323-5L [mm]
  rect 0.4x1.2 smd mask+0.05: 1(-0.65,-0.85) 2(0,-0.85) 3(0.65,-0.85) 4(0.65,0.85) 5(-0.65,0.85)
  silkscreen extent -1.22,-1.21 1.22,0.77, body extent -1.15,-1.05 1.15,1.05, height 1.1
ESD_ST0201 [mm]
  rect 0.425x0.33 smd mask+0.05: 1(-0.312,0) 2(0.312,0)
  silkscreen extent -0.55,-0.3 0.33,0.3, body extent -0.34,-0.18 0.34,0.18, height 0.34
ICC_BGA24_5X5-BALL-ARRAY_6X8_P1 [mm]
  round 0.45 smd mask+0.05: A2(-1,2) A3(0,2) A4(1,2) A5(2,2) B1(-2,1) B2(-1,1) B3(0,1) B4(1,1) B5(2,1) C1(-2,0) C2(-1,0) C3(0,0) C4(1,0) C5(2,0) D1(-2,-1) D2(-1,-1) D3(0,-1) D4(1,-1) D5(2,-1) E1(-2,-2) E2(-1,-2) E3(0,-2) E4(1,-2) E5(2,-2)
  silkscreen extent -3.05,-4.05 3.05,4.05, body extent -3.05,-4.05 3.05,4.05, height 1.2
ICC_DFN6-EPAD_3X3_P095 [mm]
  rect 0.45x0.5 smd mask+0.05: 1(-0.95,-1.3) 2(0,-1.3) 3(0.95,-1.3) 4(0.95,1.3) 5(0,1.3) 6(-0.95,1.3)
  rect 2.5x1.7 smd mask+0.05: EP(0,0)
  silkscreen extent -1.55,-1.55 1.55,1.55, body extent -1.55,-1.55 1.55,1.55, height 1
ICC_DFN8-EPAD_2X3_P050 [mm]
  rect 0.3x0.75 smd mask+0.05: 1(0.75,1.425) 2(0.25,1.425) 3(-0.25,1.425) 4(-0.75,1.425) 5(-0.75,-1.425) 6(-0.25,-1.425) 7(0.25,-1.425) 8(0.75,-1.425)
  rect 1.7x1.7 smd mask+0.05: EP(0,0)
  silkscreen extent -1.05,-1.55 1.55,1.55, body extent -1.05,-1.55 1.05,1.55, height 0.9
ICC_HLGA6_2X2_P075-1 [mm] "MCD-01447"
  rect 0.35x0.4 smd mask+0.05: 1(-0.75,0.5) 2(-0.75,-0.5) 4(0.75,-0.5) 5(0.75,0.5)
  rect 0.4x0.35 smd mask+0.05: 3(0,-0.75) 6(0,0.75)
  silkscreen extent -1.17,-1.05 1.05,1.17, body extent -1.05,-1.05 1.05,1.05, height 1.01
ICC_HLGA10_2X2_P050 [mm] "MCD-01449"
  rect 0.325x0.3 smd mask+0.05: 1(-0.763,0.25) 2(-0.763,-0.25) 6(0.763,-0.25) 7(0.763,0.25)
  rect 0.3x0.325 smd mask+0.05: 3(-0.5,-0.762) 4(0,-0.762) 5(0.5,-0.762) 8(0.5,0.763) 9(0,0.763) 10(-0.5,0.763)
  silkscreen extent -1.17,-1.05 1.05,1.17, body extent -1.05,-1.05 1.05,1.05, height 0.8
ICC_LGA12_2X2_P050_H0P7 [mm] "MCD-01448"
  rect 0.325x0.3 smd mask+0.05: 1(-0.763,0.75) 2(-0.763,0.25) 3(-0.763,-0.25) 4(-0.763,-0.75) 7(0.763,-0.75) 8(0.763,-0.25) 9(0.763,0.25) 10(0.763,0.75)
  rect 0.3x0.325 smd mask+0.05: 5(-0.25,-0.762) 6(0.25,-0.762) 11(0.25,0.763) 12(-0.25,0.763)
  silkscreen extent -1.2,-1.05 1.05,1.2, body extent -1.05,-1.05 1.05,1.05, height 0.71
ICC_LGA14_3X2P5_P050 [mm] "MCD-01387"
  rect 0.8x0.3 smd mask+0.05: 1(-1.25,0.75) 2(-1.25,0.25) 3(-1.25,-0.25) 4(-1.25,-0.75) 8(1.25,-0.75) 9(1.25,-0.25) 10(1.25,0.25) 11(1.25,0.75)
  rect 0.3x0.8 smd mask+0.05: 5(-0.5,-1) 6(0,-1) 7(0.5,-1) 12(0.5,1) 13(0,1) 14(-0.5,1)
  silkscreen extent -1.75,-1.3 1.55,1.45, body extent -1.55,-1.3 1.55,1.3, height 0.86
ICC_LGA16_6P4X3_P075_H1P5 [mm] "MCD-02257"
  rect 0.5x0.5 smd mask+0.05: A1(2.25,-1.05) A2(1.5,-1.05) A3(0.75,-1.05) A4(0,-1.05) A5(-0.75,-1.05) A6(-1.5,-1.05) A7(-2.25,-1.05) B1(2.65,0) B7(-2.65,0) C1(2.25,1.05) C2(1.5,1.05) C3(0.75,1.05) C4(0,1.05) C5(-0.75,1.05) C6(-1.5,1.05) C7(-2.25,1.05)
  rect 2.316x1.2 smd mask+0.05: B4(0,0)
  silkscreen extent -3.1,-1.5 3.1,1.5, body extent -3.1,-1.5 3.1,1.5, height 1.51
ICC_MINI-BGA24_6X8_P1 [mm] "MCD-01391"
  round 0.35 smd mask+0.05: A2(-1,2) A3(0,2) A4(1,2) A5(2,2) B1(-2,1) B2(-1,1) B3(0,1) B4(1,1) B5(2,1) C1(-2,0) C2(-1,0) C3(0,0) C4(1,0) C5(2,0) D1(-2,-1) D2(-1,-1) D3(0,-1) D4(1,-1) D5(2,-1) E1(-2,-2) E2(-1,-2) E3(0,-2) E4(1,-2) E5(2,-2)
  silkscreen extent -3.18,-4.05 3.05,4.18, body extent -3.05,-4.05 3.05,4.05, height 1.21
ICC_QFN20-EPAD_4X4_P050 [mm] "MCD-02130"
  rect 0.75x0.3 smd mask+0.05: 1(-1.925,1) 2(-1.925,0.5) 3(-1.925,0) 4(-1.925,-0.5) 5(-1.925,-1) 11(1.925,-1) 12(1.925,-0.5) 13(1.925,0) 14(1.925,0.5) 15(1.925,1)
  rect 0.3x0.75 smd mask+0.05: 6(-1,-1.925) 7(-0.5,-1.925) 8(0,-1.925) 9(0.5,-1.925) 10(1,-1.925) 16(1,1.925) 17(0.5,1.925) 18(0,1.925) 19(-0.5,1.925) 20(-1,1.925)
  rect 2.7x2.7 smd mask+0.05: 21(0,0)
  silkscreen extent -2.07,-2.07 2.07,2.07, body extent -2.13,-2.13 2.13,2.13, height 1.01
ICC_SO8_5X4_P127 [mm]
  rect 0.7x1.75 smd mask+0.05: 1(-1.905,-2.375) 2(-0.635,-2.375) 3(0.635,-2.375) 4(1.905,-2.375) 5(1.905,2.375) 6(0.635,2.375) 7(-0.635,2.375) 8(-1.905,2.375)
  silkscreen extent -2.73,-3.25 2.58,2, body extent -2.57,-3 2.57,3, height 1.75
ICC_UFBGA169_7X7_P050 [mm] "MCD-01693"
  round 0.25 smd mask+0.05: A1(-3,3) A2(-2.5,3) A3(-2,3) A4(-1.5,3) A5(-1,3) A6(-0.5,3) A7(0,3) A8(0.5,3) A9(1,3) A10(1.5,3) A11(2,3) A12(2.5,3) A13(3,3) B1(-3,2.5) B2(-2.5,2.5) B3(-2,2.5) B4(-1.5,2.5) B5(-1,2.5) B6(-0.5,2.5) B7(0,2.5) B8(0.5,2.5) B9(1,2.5) B10(1.5,2.5) B11(2,2.5) B12(2.5,2.5) B13(3,2.5) C1(-3,2) C2(-2.5,2) C3(-2,2) C4(-1.5,2) C5(-1,2) C6(-0.5,2) C7(0,2) C8(0.5,2) C9(1,2) C10(1.5,2) C11(2,2) C12(2.5,2) C13(3,2) D1(-3,1.5) D2(-2.5,1.5) D3(-2,1.5) D4(-1.5,1.5) D5(-1,1.5) D6(-0.5,1.5) D7(0,1.5) D8(0.5,1.5) D9(1,1.5) D10(1.5,1.5) D11(2,1.5) D12(2.5,1.5) D13(3,1.5) E1(-3,1) E2(-2.5,1) E3(-2,1) E4(-1.5,1) E5(-1,1) E6(-0.5,1) E7(0,1) E8(0.5,1) E9(1,1) E10(1.5,1) E11(2,1) E12(2.5,1) E13(3,1) F1(-3,0.5) F2(-2.5,0.5) F3(-2,0.5) F4(-1.5,0.5) F5(-1,0.5) F6(-0.5,0.5) F7(0,0.5) F8(0.5,0.5) F9(1,0.5) F10(1.5,0.5) F11(2,0.5) F12(2.5,0.5) F13(3,0.5) G1(-3,0) G2(-2.5,0) G3(-2,0) G4(-1.5,0) G5(-1,0) G6(-0.5,0) G7(0,0) G8(0.5,0) G9(1,0) G10(1.5,0) G11(2,0) G12(2.5,0) G13(3,0) H1(-3,-0.5) H2(-2.5,-0.5) H3(-2,-0.5) H4(-1.5,-0.5) H5(-1,-0.5) H6(-0.5,-0.5) H7(0,-0.5) H8(0.5,-0.5) H9(1,-0.5) H10(1.5,-0.5) H11(2,-0.5) H12(2.5,-0.5) H13(3,-0.5) J1(-3,-1) J2(-2.5,-1) J3(-2,-1) J4(-1.5,-1) J5(-1,-1) J6(-0.5,-1) J7(0,-1) J8(0.5,-1) J9(1,-1) J10(1.5,-1) J11(2,-1) J12(2.5,-1) J13(3,-1) K1(-3,-1.5) K2(-2.5,-1.5) K3(-2,-1.5) K4(-1.5,-1.5) K5(-1,-1.5) K6(-0.5,-1.5) K7(0,-1.5) K8(0.5,-1.5) K9(1,-1.5) K10(1.5,-1.5) K11(2,-1.5) K12(2.5,-1.5) K13(3,-1.5) L1(-3,-2) L2(-2.5,-2) L3(-2,-2) L4(-1.5,-2) L5(-1,-2) L6(-0.5,-2) L7(0,-2) L8(0.5,-2) L9(1,-2) L10(1.5,-2) L11(2,-2) L12(2.5,-2) L13(3,-2) M1(-3,-2.5) M2(-2.5,-2.5) M3(-2,-2.5) M4(-1.5,-2.5) M5(-1,-2.5) M6(-0.5,-2.5) M7(0,-2.5) M8(0.5,-2.5) M9(1,-2.5) M10(1.5,-2.5) M11(2,-2.5) M12(2.5,-2.5) M13(3,-2.5) N1(-3,-3) N2(-2.5,-3) N3(-2,-3) N4(-1.5,-3) N5(-1,-3) N6(-0.5,-3) N7(0,-3) N8(0.5,-3) N9(1,-3) N10(1.5,-3) N11(2,-3) N12(2.5,-3) N13(3,-3)
  silkscreen extent -3.7,-3.57 3.57,3.7, body extent -3.57,-3.57 3.57,3.57, height 0.61
ICC_UFBGA201_176+25_10X10_P065 [mm] "IPC"
  round 0.25 smd mask+0.05: A1(-4.55,4.55) A2(-3.9,4.55) A3(-3.25,4.55) A4(-2.6,4.55) A5(-1.95,4.55) A6(-1.3,4.55) A7(-0.65,4.55) A8(0,4.55) A9(0.65,4.55) A10(1.3,4.55) A11(1.95,4.55) A12(2.6,4.55) A13(3.25,4.55) A14(3.9,4.55) A15(4.55,4.55) B1(-4.55,3.9) B2(-3.9,3.9) B3(-3.25,3.9) B4(-2.6,3.9) B5(-1.95,3.9) B6(-1.3,3.9) B7(-0.65,3.9) B8(0,3.9) B9(0.65,3.9) B10(1.3,3.9) B11(1.95,3.9) B12(2.6,3.9) B13(3.25,3.9) B14(3.9,3.9) B15(4.55,3.9) C1(-4.55,3.25) C2(-3.9,3.25) C3(-3.25,3.25) C4(-2.6,3.25) C5(-1.95,3.25) C6(-1.3,3.25) C7(-0.65,3.25) C8(0,3.25) C9(0.65,3.25) C10(1.3,3.25) C11(1.95,3.25) C12(2.6,3.25) C13(3.25,3.25) C14(3.9,3.25) C15(4.55,3.25) D1(-4.55,2.6) D2(-3.9,2.6) D3(-3.25,2.6) D4(-2.6,2.6) D5(-1.95,2.6) D6(-1.3,2.6) D7(-0.65,2.6) D8(0,2.6) D9(0.65,2.6) D10(1.3,2.6) D11(1.95,2.6) D12(2.6,2.6) D13(3.25,2.6) D14(3.9,2.6) D15(4.55,2.6) E1(-4.55,1.95) E2(-3.9,1.95) E3(-3.25,1.95) E4(-2.6,1.95) E12(2.6,1.95) E13(3.25,1.95) E14(3.9,1.95) E15(4.55,1.95) F1(-4.55,1.3) F2(-3.9,1.3) F3(-3.25,1.3) F4(-2.6,1.3) F6(-1.3,1.3) F7(-0.65,1.3) F8(0,1.3) F9(0.65,1.3) F10(1.3,1.3) F12(2.6,1.3) F13(3.25,1.3) F14(3.9,1.3) F15(4.55,1.3) G1(-4.55,0.65) G2(-3.9,0.65) G3(-3.25,0.65) G4(-2.6,0.65) G6(-1.3,0.65) G7(-0.65,0.65) G8(0,0.65) G9(0.65,0.65) G10(1.3,0.65) G12(2.6,0.65) G13(3.25,0.65) G14(3.9,0.65) G15(4.55,0.65) H1(-4.55,0) H2(-3.9,0) H3(-3.25,0) H4(-2.6,0) H6(-1.3,0) H7(-0.65,0) H8(0,0) H9(0.65,0) H10(1.3,0) H12(2.6,0) H13(3.25,0) H14(3.9,0) H15(4.55,0) J1(-4.55,-0.65) J2(-3.9,-0.65) J3(-3.25,-0.65) J4(-2.6,-0.65) J6(-1.3,-0.65) J7(-0.65,-0.65) J8(0,-0.65) J9(0.65,-0.65) J10(1.3,-0.65) J12(2.6,-0.65) J13(3.25,-0.65) J14(3.9,-0.65) J15(4.55,-0.65) K1(-4.55,-1.3) K2(-3.9,-1.3) K3(-3.25,-1.3) K4(-2.6,-1.3) K6(-1.3,-1.3) K7(-0.65,-1.3) K8(0,-1.3) K9(0.65,-1.3) K10(1.3,-1.3) K12(2.6,-1.3) K13(3.25,-1.3) K14(3.9,-1.3) K15(4.55,-1.3) L1(-4.55,-1.95) L2(-3.9,-1.95) L3(-3.25,-1.95) L4(-2.6,-1.95) L12(2.6,-1.95) L13(3.25,-1.95) L14(3.9,-1.95) L15(4.55,-1.95) M1(-4.55,-2.6) M2(-3.9,-2.6) M3(-3.25,-2.6) M4(-2.6,-2.6) M5(-1.95,-2.6) M6(-1.3,-2.6) M7(-0.65,-2.6) M8(0,-2.6) M9(0.65,-2.6) M10(1.3,-2.6) M11(1.95,-2.6) M12(2.6,-2.6) M13(3.25,-2.6) M14(3.9,-2.6) M15(4.55,-2.6) N1(-4.55,-3.25) N2(-3.9,-3.25) N3(-3.25,-3.25) N4(-2.6,-3.25) N5(-1.95,-3.25) N6(-1.3,-3.25) N7(-0.65,-3.25) N8(0,-3.25) N9(0.65,-3.25) N10(1.3,-3.25) N11(1.95,-3.25) N12(2.6,-3.25) N13(3.25,-3.25) N14(3.9,-3.25) N15(4.55,-3.25) P1(-4.55,-3.9) P2(-3.9,-3.9) P3(-3.25,-3.9) P4(-2.6,-3.9) P5(-1.95,-3.9) P6(-1.3,-3.9) P7(-0.65,-3.9) P8(0,-3.9) P9(0.65,-3.9) P10(1.3,-3.9) P11(1.95,-3.9) P12(2.6,-3.9) P13(3.25,-3.9) P14(3.9,-3.9) P15(4.55,-3.9) R1(-4.55,-4.55) R2(-3.9,-4.55) R3(-3.25,-4.55) R4(-2.6,-4.55) R5(-1.95,-4.55) R6(-1.3,-4.55) R7(-0.65,-4.55) R8(0,-4.55) R9(0.65,-4.55) R10(1.3,-4.55) R11(1.95,-4.55) R12(2.6,-4.55) R13(3.25,-4.55) R14(3.9,-4.55) R15(4.55,-4.55)
  silkscreen extent -5.22,-5.07 5.07,5.23, body extent -5.07,-5.07 5.07,5.07, height 0.61
ICC_UFQFN16-EPAD_2P6X1P8_P040 [mm]
  rect 0.2x0.35 smd mask+0.05: 1(-0.6,-0.775) 2(-0.2,-0.775) 3(0.2,-0.775) 4(0.6,-0.775) 9(0.6,0.775) 10(0.2,0.775) 11(-0.2,0.775) 12(-0.6,0.775)
  rect 0.35x0.2 smd mask+0.05: 5(1.175,-0.6) 6(1.175,-0.2) 7(1.175,0.2) 8(1.175,0.6) 13(-1.175,0.6) 14(-1.175,0.2) 15(-1.175,-0.2) 16(-1.175,-0.6)
  rect 1.6x0.8 smd mask+0.05: 17(0,0)
  silkscreen extent -1.33,-0.92 1.33,0.92, body extent -1.33,-0.92 1.33,0.92, height 0.56
ICC_VISHAY_VEML6030_2X2_P065 [mm] "MCD-02336"
  rect 0.55x0.3 smd mask+0.05: 1(0.875,-0.65) 2(0.875,0) 3(0.875,0.65) 4(-0.875,0.65) 5(-0.875,0) 6(-0.875,-0.65)
  silkscreen extent -1.05,-1.17 1.22,1.05, body extent -1,-1 1,1, height 0.87
L0805_H0P9 [mm]
  rect 1.1x1.6 smd mask+0.05: 1(-0.75,0) 2(0.75,0)
  silkscreen extent -0.08,-0.7 0.08,0.7, body extent -1.07,-0.7 1.07,0.7, height 1.2
LED_0603_GREEN [mm]
  rect 0.8x0.8 smd mask+0.05: 1(-0.75,0) 2(0.75,0)
  silkscreen extent -0.25,-0.4 1.25,0.4, body extent -0.8,-0.4 0.8,0.4, height 0.6
LED_0603_OSRAM_LG-Q396-PS-35_GREEN_1A2K_H0P4 [mm]
  rect 0.8x0.8 smd mask+0.05: 1(-0.75,0) 2(0.75,0)
  silkscreen extent -0.85,-0.53 1.28,0.53, body extent -0.85,-0.45 0.85,0.45, height 0.6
